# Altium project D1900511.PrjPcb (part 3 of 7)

## Sheet ISC_R2_SH2.SchDoc: ISC System Wiring Diagram
size C; DrawnBy: Filiberto Clara; Engineer: Filiberto Clara; Organization: LIGO Laboratory; Address1: California Institute of Technology; Address2: Massachusetts Institute of Technology; DocumentNumber: D1900511; Revision: V11; SheetNumber: 14; SheetTotal: 39
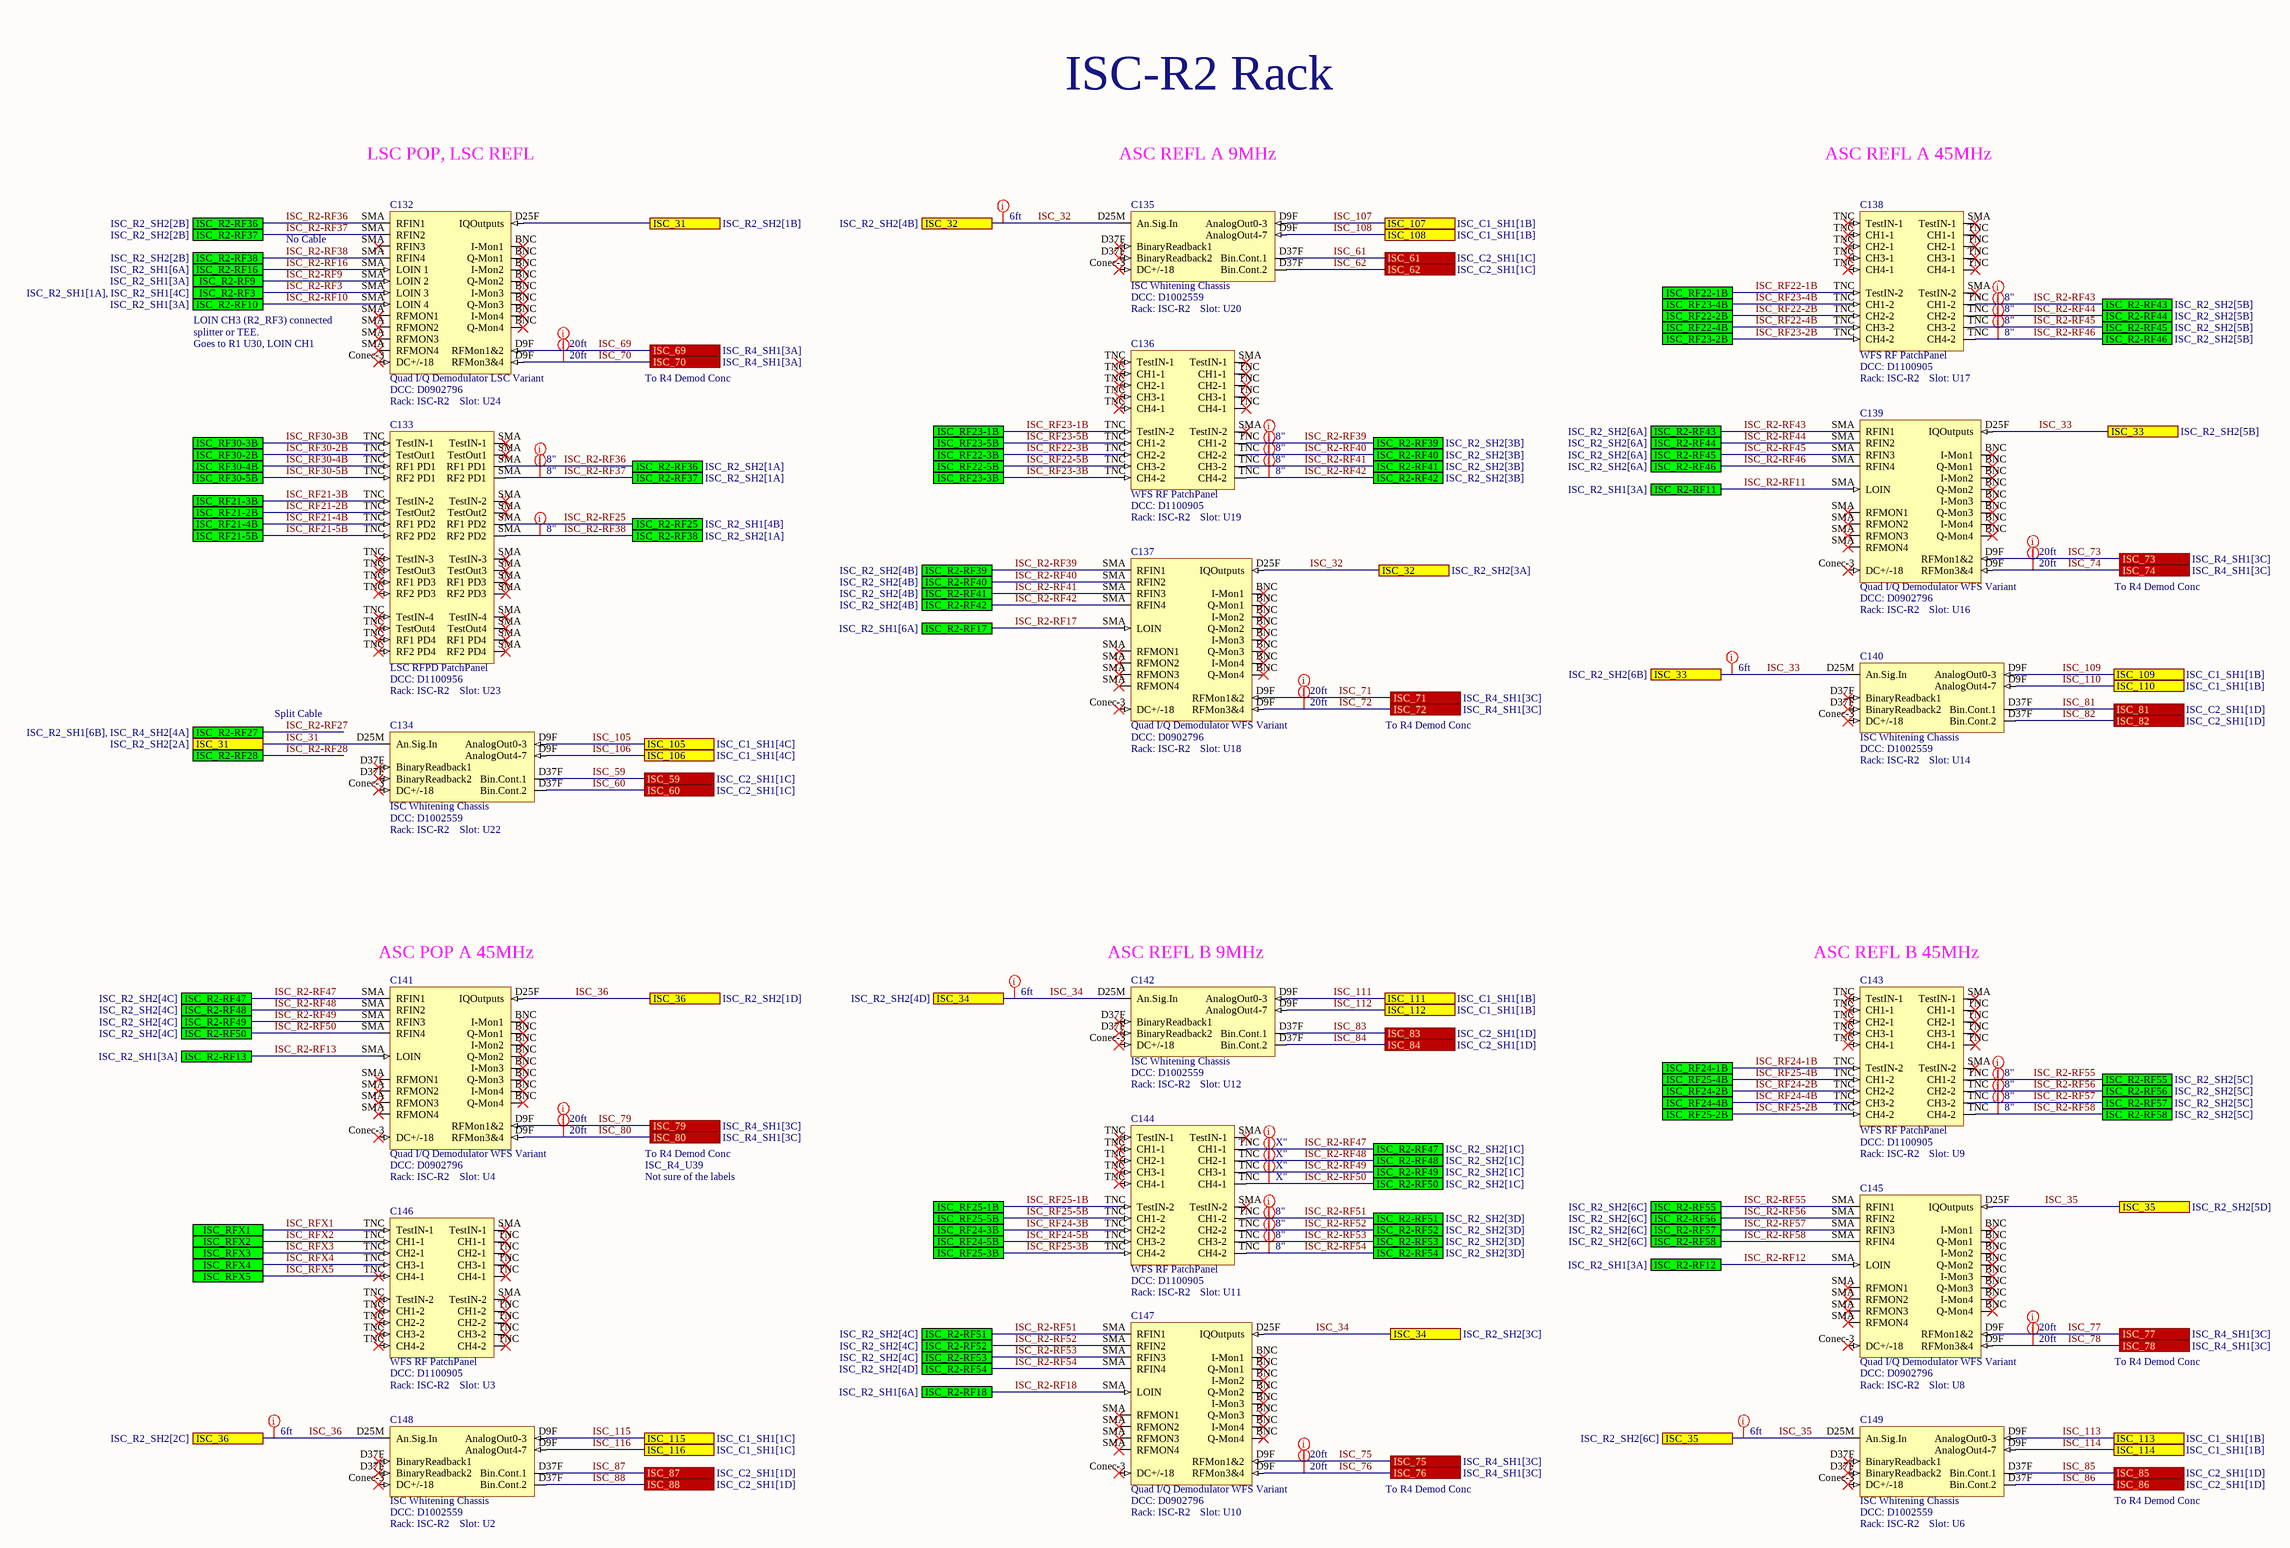
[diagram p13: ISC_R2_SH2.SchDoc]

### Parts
C132  Quad I/Q Demodulator LSC Variant  DCC: D0902796  Rack: ISC-R2  Slot: U24
C133  LSC RFPD PatchPanel  DCC: D1100956  Rack: ISC-R2  Slot: U23
C134  ISC Whitening Chassis  DCC: D1002559  Rack: ISC-R2  Slot: U22
C135  ISC Whitening Chassis  DCC: D1002559  Rack: ISC-R2  Slot: U20
C136  WFS RF PatchPanel  DCC: D1100905  Rack: ISC-R2  Slot: U19
C137  Quad I/Q Demodulator WFS Variant  DCC: D0902796  Rack: ISC-R2  Slot: U18
C138  WFS RF PatchPanel  DCC: D1100905  Rack: ISC-R2  Slot: U17
C139  Quad I/Q Demodulator WFS Variant  DCC: D0902796  Rack: ISC-R2  Slot: U16
C140  ISC Whitening Chassis  DCC: D1002559  Rack: ISC-R2  Slot: U14
C141  Quad I/Q Demodulator WFS Variant  DCC: D0902796  Rack: ISC-R2  Slot: U4
C142  ISC Whitening Chassis  DCC: D1002559  Rack: ISC-R2  Slot: U12
C143  WFS RF PatchPanel  DCC: D1100905  Rack: ISC-R2  Slot: U9
C144  WFS RF PatchPanel  DCC: D1100905  Rack: ISC-R2  Slot: U11
C145  Quad I/Q Demodulator WFS Variant  DCC: D0902796  Rack: ISC-R2  Slot: U8
C146  WFS RF PatchPanel  DCC: D1100905  Rack: ISC-R2  Slot: U3
C147  Quad I/Q Demodulator WFS Variant  DCC: D0902796  Rack: ISC-R2  Slot: U10
C148  ISC Whitening Chassis  DCC: D1002559  Rack: ISC-R2  Slot: U2
C149  ISC Whitening Chassis  DCC: D1002559  Rack: ISC-R2  Slot: U6

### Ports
ISC_31 (see ISC_R2_SH2[1B]), ISC_31 (see ISC_R2_SH2[2A]), ISC_32 (see ISC_R2_SH2[3A]), ISC_32 (see ISC_R2_SH2[4B]), ISC_33 (see ISC_R2_SH2[5B]), ISC_33 (see ISC_R2_SH2[6B]), ISC_34 (see ISC_R2_SH2[3C]), ISC_34 (see ISC_R2_SH2[4D]), ISC_35 (see ISC_R2_SH2[5D]), ISC_35 (see ISC_R2_SH2[6C]), ISC_36 (see ISC_R2_SH2[1D]), ISC_36 (see ISC_R2_SH2[2C]), ISC_59 (see ISC_C2_SH1[1C]), ISC_60 (see ISC_C2_SH1[1C]), ISC_61 (see ISC_C2_SH1[1C]), ISC_62 (see ISC_C2_SH1[1C]), ISC_69 (see ISC_R4_SH1[3A]), ISC_70 (see ISC_R4_SH1[3A]), ISC_71 (see ISC_R4_SH1[3C]), ISC_72 (see ISC_R4_SH1[3C]), ISC_73 (see ISC_R4_SH1[3C]), ISC_74 (see ISC_R4_SH1[3C]), ISC_75 (see ISC_R4_SH1[3C]), ISC_76 (see ISC_R4_SH1[3C]), ISC_77 (see ISC_R4_SH1[3C]), ISC_78 (see ISC_R4_SH1[3C]), ISC_79 (see ISC_R4_SH1[3C]), ISC_80 (see ISC_R4_SH1[3C]), ISC_81 (see ISC_C2_SH1[1D]), ISC_82 (see ISC_C2_SH1[1D]), ISC_83 (see ISC_C2_SH1[1D]), ISC_84 (see ISC_C2_SH1[1D]), ISC_85 (see ISC_C2_SH1[1D]), ISC_86 (see ISC_C2_SH1[1D]), ISC_87 (see ISC_C2_SH1[1D]), ISC_88 (see ISC_C2_SH1[1D]), ISC_105 (see ISC_C1_SH1[4C]), ISC_106 (see ISC_C1_SH1[4C]), ISC_107 (see ISC_C1_SH1[1B]), ISC_108 (see ISC_C1_SH1[1B]), ISC_109 (see ISC_C1_SH1[1B]), ISC_110 (see ISC_C1_SH1[1B]), ISC_111 (see ISC_C1_SH1[1B]), ISC_112 (see ISC_C1_SH1[1B]), ISC_113 (see ISC_C1_SH1[1B]), ISC_114 (see ISC_C1_SH1[1B]), ISC_115 (see ISC_C1_SH1[1C]), ISC_116 (see ISC_C1_SH1[1C]), ISC_R2-RF3 (see ISC_R2_SH1[1A], ISC_R2_SH1[4C]), ISC_R2-RF9 (see ISC_R2_SH1[3A]), ISC_R2-RF10 (see ISC_R2_SH1[3A]), ISC_R2-RF11 (see ISC_R2_SH1[3A]), ISC_R2-RF12 (see ISC_R2_SH1[3A]), ISC_R2-RF13 (see ISC_R2_SH1[3A]), ISC_R2-RF16 (see ISC_R2_SH1[6A]), ISC_R2-RF17 (see ISC_R2_SH1[6A]), ISC_R2-RF18 (see ISC_R2_SH1[6A]), ISC_R2-RF25 (see ISC_R2_SH1[4B]), ISC_R2-RF27 (see ISC_R2_SH1[6B], ISC_R4_SH2[4A]), ISC_R2-RF28, ISC_R2-RF36 (see ISC_R2_SH2[1A]), ISC_R2-RF36 (see ISC_R2_SH2[2B]), ISC_R2-RF37 (see ISC_R2_SH2[1A]), ISC_R2-RF37 (see ISC_R2_SH2[2B]), ISC_R2-RF38 (see ISC_R2_SH2[1A]), ISC_R2-RF38 (see ISC_R2_SH2[2B]), ISC_R2-RF39 (see ISC_R2_SH2[3B]), ISC_R2-RF39 (see ISC_R2_SH2[4B]), ISC_R2-RF40 (see ISC_R2_SH2[3B]), ISC_R2-RF40 (see ISC_R2_SH2[4B]), ISC_R2-RF41 (see ISC_R2_SH2[3B]), ISC_R2-RF41 (see ISC_R2_SH2[4B]), ISC_R2-RF42 (see ISC_R2_SH2[3B]), ISC_R2-RF42 (see ISC_R2_SH2[4B]), ISC_R2-RF43 (see ISC_R2_SH2[5B]), ISC_R2-RF43 (see ISC_R2_SH2[6A]), ISC_R2-RF44 (see ISC_R2_SH2[5B]), ISC_R2-RF44 (see ISC_R2_SH2[6A]), ISC_R2-RF45 (see ISC_R2_SH2[5B]), ISC_R2-RF45 (see ISC_R2_SH2[6A]), ISC_R2-RF46 (see ISC_R2_SH2[5B]), ISC_R2-RF46 (see ISC_R2_SH2[6A]), ISC_R2-RF47 (see ISC_R2_SH2[1C]), ISC_R2-RF47 (see ISC_R2_SH2[4C]), ISC_R2-RF48 (see ISC_R2_SH2[1C]), ISC_R2-RF48 (see ISC_R2_SH2[4C]), ISC_R2-RF49 (see ISC_R2_SH2[1C]), ISC_R2-RF49 (see ISC_R2_SH2[4C]), ISC_R2-RF50 (see ISC_R2_SH2[1C]), ISC_R2-RF50 (see ISC_R2_SH2[4C]), ISC_R2-RF51 (see ISC_R2_SH2[3D]), ISC_R2-RF51 (see ISC_R2_SH2[4C]), ISC_R2-RF52 (see ISC_R2_SH2[3D]), ISC_R2-RF52 (see ISC_R2_SH2[4C]), ISC_R2-RF53 (see ISC_R2_SH2[3D]), ISC_R2-RF53 (see ISC_R2_SH2[4C]), ISC_R2-RF54 (see ISC_R2_SH2[3D]), ISC_R2-RF54 (see ISC_R2_SH2[4D]), ISC_R2-RF55 (see ISC_R2_SH2[5C]), ISC_R2-RF55 (see ISC_R2_SH2[6C]), ISC_R2-RF56 (see ISC_R2_SH2[5C]), ISC_R2-RF56 (see ISC_R2_SH2[6C]), ISC_R2-RF57 (see ISC_R2_SH2[5C]), ISC_R2-RF57 (see ISC_R2_SH2[6C]), ISC_R2-RF58 (see ISC_R2_SH2[5C]), ISC_R2-RF58 (see ISC_R2_SH2[6C]), ISC_RF21-2B, ISC_RF21-3B, ISC_RF21-4B, ISC_RF21-5B, ISC_RF22-1B, ISC_RF22-2B, ISC_RF22-3B, ISC_RF22-4B, ISC_RF22-5B, ISC_RF23-1B, ISC_RF23-2B, ISC_RF23-3B, ISC_RF23-4B, ISC_RF23-5B, ISC_RF24-1B, ISC_RF24-2B, ISC_RF24-3B, ISC_RF24-4B, ISC_RF24-5B, ISC_RF25-1B, ISC_RF25-2B, ISC_RF25-3B, ISC_RF25-4B, ISC_RF25-5B, ISC_RF30-2B, ISC_RF30-3B, ISC_RF30-4B, ISC_RF30-5B, ISC_RFX1, ISC_RFX2, ISC_RFX3, ISC_RFX4, ISC_RFX5

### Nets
ISC_31: C132.D25F(IQOutputs) C134.D25M(An.Sig.In) ; port ISC_31
ISC_32: C135.D25M(An.Sig.In) C137.D25F(IQOutputs) ; port ISC_32
ISC_33: C139.D25F(IQOutputs) C140.D25M(An.Sig.In) ; port ISC_33
ISC_34: C142.D25M(An.Sig.In) C147.D25F(IQOutputs) ; port ISC_34
ISC_35: C145.D25F(IQOutputs) C149.D25M(An.Sig.In) ; port ISC_35
ISC_36: C141.D25F(IQOutputs) C148.D25M(An.Sig.In) ; port ISC_36
ISC_59: C134.D37F(BinaryReadback1) ; port ISC_59
ISC_60: C134.D37F(Bin.Cont.2) ; port ISC_60
ISC_61: C135.D37F(BinaryReadback1) ; port ISC_61
ISC_62: C135.D37F(Bin.Cont.2) ; port ISC_62
ISC_69: C132.D9F(RFMon1&2) ; port ISC_69
ISC_70: C132.D9F(RFMon3&4) ; port ISC_70
ISC_71: C137.D9F(RFMon1&2) ; port ISC_71
ISC_72: C137.D9F(RFMon3&4) ; port ISC_72
ISC_73: C139.D9F(RFMon1&2) ; port ISC_73
ISC_74: C139.D9F(RFMon3&4) ; port ISC_74
ISC_75: C147.D9F(RFMon1&2) ; port ISC_75
ISC_76: C147.D9F(RFMon3&4) ; port ISC_76
ISC_77: C145.D9F(RFMon1&2) ; port ISC_77
ISC_78: C145.D9F(RFMon3&4) ; port ISC_78
ISC_79: C141.D9F(RFMon1&2) ; port ISC_79
ISC_80: C141.D9F(RFMon3&4) ; port ISC_80
ISC_81: C140.D37F(BinaryReadback1) ; port ISC_81
ISC_82: C140.D37F(Bin.Cont.2) ; port ISC_82
ISC_83: C142.D37F(BinaryReadback1) ; port ISC_83
ISC_84: C142.D37F(Bin.Cont.2) ; port ISC_84
ISC_85: C149.D37F(BinaryReadback1) ; port ISC_85
ISC_86: C149.D37F(Bin.Cont.2) ; port ISC_86
ISC_87: C148.D37F(BinaryReadback1) ; port ISC_87
ISC_88: C148.D37F(Bin.Cont.2) ; port ISC_88
ISC_105: C134.D9F(AnalogOut0-3) ; port ISC_105
ISC_106: C134.D9F(AnalogOut4-7) ; port ISC_106
ISC_107: C135.D9F(AnalogOut0-3) ; port ISC_107
ISC_108: C135.D9F(AnalogOut4-7) ; port ISC_108
ISC_109: C140.D9F(AnalogOut0-3) ; port ISC_109
ISC_110: C140.D9F(AnalogOut4-7) ; port ISC_110
ISC_111: C142.D9F(AnalogOut0-3) ; port ISC_111
ISC_112: C142.D9F(AnalogOut4-7) ; port ISC_112
ISC_113: C149.D9F(AnalogOut0-3) ; port ISC_113
ISC_114: C149.D9F(AnalogOut4-7) ; port ISC_114
ISC_115: C148.D9F(AnalogOut0-3) ; port ISC_115
ISC_116: C148.D9F(AnalogOut4-7) ; port ISC_116
ISC_R2-RF3: C132.SMA(LOIN_3) ; port ISC_R2-RF3
ISC_R2-RF9: C132.SMA(LOIN_2) ; port ISC_R2-RF9
ISC_R2-RF10: C132.SMA(LOIN_4) ; port ISC_R2-RF10
ISC_R2-RF11: C139.SMA(LOIN) ; port ISC_R2-RF11
ISC_R2-RF12: C145.SMA(LOIN) ; port ISC_R2-RF12
ISC_R2-RF13: C141.SMA(LOIN) ; port ISC_R2-RF13
ISC_R2-RF16: C132.SMA(LOIN_1) ; port ISC_R2-RF16
ISC_R2-RF17: C137.SMA(LOIN) ; port ISC_R2-RF17
ISC_R2-RF18: C147.SMA(LOIN) ; port ISC_R2-RF18
ISC_R2-RF25: C133.SMA(RF1_PD2) ; port ISC_R2-RF25
ISC_R2-RF36: C132.SMA(RFIN1) C133.SMA(TestIN-1) ; port ISC_R2-RF36
ISC_R2-RF37: C132.SMA(RFIN2) C133.SMA(RF2_PD1) ; port ISC_R2-RF37
ISC_R2-RF38: C132.SMA(RFIN4) C133.SMA(RF2_PD2) ; port ISC_R2-RF38
ISC_R2-RF39: C136.TNC(CH1-2) C137.SMA(RFIN1) ; port ISC_R2-RF39
ISC_R2-RF40: C136.TNC(CH2-2) C137.SMA(RFIN2) ; port ISC_R2-RF40
ISC_R2-RF41: C136.TNC(CH3-2) C137.SMA(RFIN3) ; port ISC_R2-RF41
ISC_R2-RF42: C136.TNC(CH4-2) C137.SMA(RFIN4) ; port ISC_R2-RF42
ISC_R2-RF43: C138.TNC(CH1-2) C139.SMA(RFIN1) ; port ISC_R2-RF43
ISC_R2-RF44: C138.TNC(CH2-2) C139.SMA(RFIN2) ; port ISC_R2-RF44
ISC_R2-RF45: C138.TNC(CH3-2) C139.SMA(RFIN3) ; port ISC_R2-RF45
ISC_R2-RF46: C138.TNC(CH4-2) C139.SMA(RFIN4) ; port ISC_R2-RF46
ISC_R2-RF47: C141.SMA(RFIN1) C144.TNC(CH1-1) ; port ISC_R2-RF47
ISC_R2-RF48: C141.SMA(RFIN2) C144.TNC(CH2-1) ; port ISC_R2-RF48
ISC_R2-RF49: C141.SMA(RFIN3) C144.TNC(CH3-1) ; port ISC_R2-RF49
ISC_R2-RF50: C141.SMA(RFIN4) C144.TNC(CH4-1) ; port ISC_R2-RF50
ISC_R2-RF51: C144.TNC(CH1-2) C147.SMA(RFIN1) ; port ISC_R2-RF51
ISC_R2-RF52: C144.TNC(CH2-2) C147.SMA(RFIN2) ; port ISC_R2-RF52
ISC_R2-RF53: C144.TNC(CH3-2) C147.SMA(RFIN3) ; port ISC_R2-RF53
ISC_R2-RF54: C144.TNC(CH4-2) C147.SMA(RFIN4) ; port ISC_R2-RF54
ISC_R2-RF55: C143.TNC(CH1-2) C145.SMA(RFIN1) ; port ISC_R2-RF55
ISC_R2-RF56: C143.TNC(CH2-2) C145.SMA(RFIN2) ; port ISC_R2-RF56
ISC_R2-RF57: C143.TNC(CH3-2) C145.SMA(RFIN3) ; port ISC_R2-RF57
ISC_R2-RF58: C143.TNC(CH4-2) C145.SMA(RFIN4) ; port ISC_R2-RF58
ISC_RF21-2B: C133.TNC(TestOut2) ; port ISC_RF21-2B
ISC_RF21-3B: C133.TNC(TestIN-2) ; port ISC_RF21-3B
ISC_RF21-4B: C133.TNC(RF1_PD2) ; port ISC_RF21-4B
ISC_RF21-5B: C133.TNC(RF2_PD2) ; port ISC_RF21-5B
ISC_RF22-1B: C138.TNC(TestIN-1) ; port ISC_RF22-1B
ISC_RF22-2B: C138.TNC(CH2-2) ; port ISC_RF22-2B
ISC_RF22-3B: C136.TNC(CH2-2) ; port ISC_RF22-3B
ISC_RF22-4B: C138.TNC(CH3-2) ; port ISC_RF22-4B
ISC_RF22-5B: C136.TNC(CH3-2) ; port ISC_RF22-5B
ISC_RF23-1B: C136.TNC(TestIN-1) ; port ISC_RF23-1B
ISC_RF23-2B: C138.TNC(CH4-2) ; port ISC_RF23-2B
ISC_RF23-3B: C136.TNC(CH4-2) ; port ISC_RF23-3B
ISC_RF23-4B: C138.TNC(CH1-2) ; port ISC_RF23-4B
ISC_RF23-5B: C136.TNC(CH1-2) ; port ISC_RF23-5B
ISC_RF24-1B: C143.TNC(TestIN-1) ; port ISC_RF24-1B
ISC_RF24-2B: C143.TNC(CH2-2) ; port ISC_RF24-2B
ISC_RF24-3B: C144.TNC(CH2-2) ; port ISC_RF24-3B
ISC_RF24-4B: C143.TNC(CH3-2) ; port ISC_RF24-4B
ISC_RF24-5B: C144.TNC(CH3-2) ; port ISC_RF24-5B
ISC_RF25-1B: C144.TNC(TestIN-1) ; port ISC_RF25-1B
ISC_RF25-2B: C143.TNC(CH4-2) ; port ISC_RF25-2B
ISC_RF25-3B: C144.TNC(CH4-2) ; port ISC_RF25-3B
ISC_RF25-4B: C143.TNC(CH1-2) ; port ISC_RF25-4B
ISC_RF25-5B: C144.TNC(CH1-2) ; port ISC_RF25-5B
ISC_RF30-2B: C133.TNC(TestOut1) ; port ISC_RF30-2B
ISC_RF30-3B: C133.TNC(TestIN-1) ; port ISC_RF30-3B
ISC_RF30-4B: C133.TNC(RF1_PD1) ; port ISC_RF30-4B
ISC_RF30-5B: C133.TNC(RF2_PD1) ; port ISC_RF30-5B
ISC_RFX1: C146.TNC(TestIN-1) ; port ISC_RFX1
ISC_RFX2: C146.TNC(CH1-1) ; port ISC_RFX2
ISC_RFX3: C146.TNC(CH2-1) ; port ISC_RFX3
ISC_RFX4: C146.TNC(CH3-1) ; port ISC_RFX4
ISC_RFX5: C146.TNC(CH4-1) ; port ISC_RFX5

Not connected (* = marked no-connect by the designer): C132 BNC(I-Mon1)* Conec-3(DC+/-18)*; C134 Conec-3(DC+/-18)*; C135 Conec-3(DC+/-18)*; C136 SMA(TestIN-1)*; C137 BNC(I-Mon1)* Conec-3(DC+/-18)*; C138 SMA(TestIN-1)*; C139 BNC(I-Mon1)* Conec-3(DC+/-18)*; C140 Conec-3(DC+/-18)*; C141 BNC(I-Mon1)* Conec-3(DC+/-18)*; C142 Conec-3(DC+/-18)*; C143 SMA(TestIN-1)*; C144 SMA(TestIN-1)*; C145 BNC(I-Mon1)* Conec-3(DC+/-18)*; C146 SMA(TestIN-1)*; C147 BNC(I-Mon1)* Conec-3(DC+/-18)*; C148 Conec-3(DC+/-18)*; C149 Conec-3(DC+/-18)*

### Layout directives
Length: 6ft: ISC_32, ISC_33, ISC_34, ISC_35, ISC_36
Length: 20ft: ISC_69, ISC_70, ISC_71, ISC_72, ISC_73, ISC_74, ISC_75, ISC_76, ISC_77, ISC_78, ISC_79, ISC_80
Length: 8": ISC_R2-RF36, ISC_R2-RF37, ISC_R2-RF38, ISC_R2-RF39, ISC_R2-RF40, ISC_R2-RF41, ISC_R2-RF42, ISC_R2-RF43, ISC_R2-RF44, ISC_R2-RF45, ISC_R2-RF46, ISC_R2-RF51, ISC_R2-RF52, ISC_R2-RF53, ISC_R2-RF54, ISC_R2-RF55, ISC_R2-RF56, ISC_R2-RF57, ISC_R2-RF58
Length: X": ISC_R2-RF47, ISC_R2-RF48, ISC_R2-RF49, ISC_R2-RF50

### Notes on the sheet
- ISC-R2 Rack
- LSC POP, LSC REFL
- ASC REFL A 9MHz
- ASC REFL A 45MHz
- No Cable
- LOIN CH3 (R2_RF3) connected
- splitter or TEE.
- Goes to R1 U30, LOIN CH1
- To R4 Demod Conc
- Split Cable
- (near C141) ASC POP A 45MHz
- (near C142) ASC REFL B 9MHz
- (near C143) ASC REFL B 45MHz
- ISC_R4_U39
- Not sure of the labels

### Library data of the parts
C132 = QuadIQdemod_LSC: Serial: Sxxxxxxx; System: ISC
C133 = LSC RFPD PatchPanel: Serial: Sxxxxxxx; System: ISC
C134 C135 C140 C142 C148 C149 = ISC Whitening: Serial: Sxxxxxxx
C136 C138 C143 C144 C146 = WFS RFPD PatchPanel: Serial: Sxxxxxxx; System: ISC
C137 C139 C141 C145 C147 = QuadIQdemod_WFS: Serial: Sxxxxxxx; System: ISC

## Sheet ISC_R4_SH1.SchDoc: ISC System Wiring Diagram
size B; DrawnBy: Filiberto Clara; Engineer: Filiberto Clara; Organization: LIGO Laboratory; Address1: California Institute of Technology; Address2: Massachusetts Institute of Technology; DocumentNumber: D1900511; Revision: V11; SheetNumber: 15; SheetTotal: 39
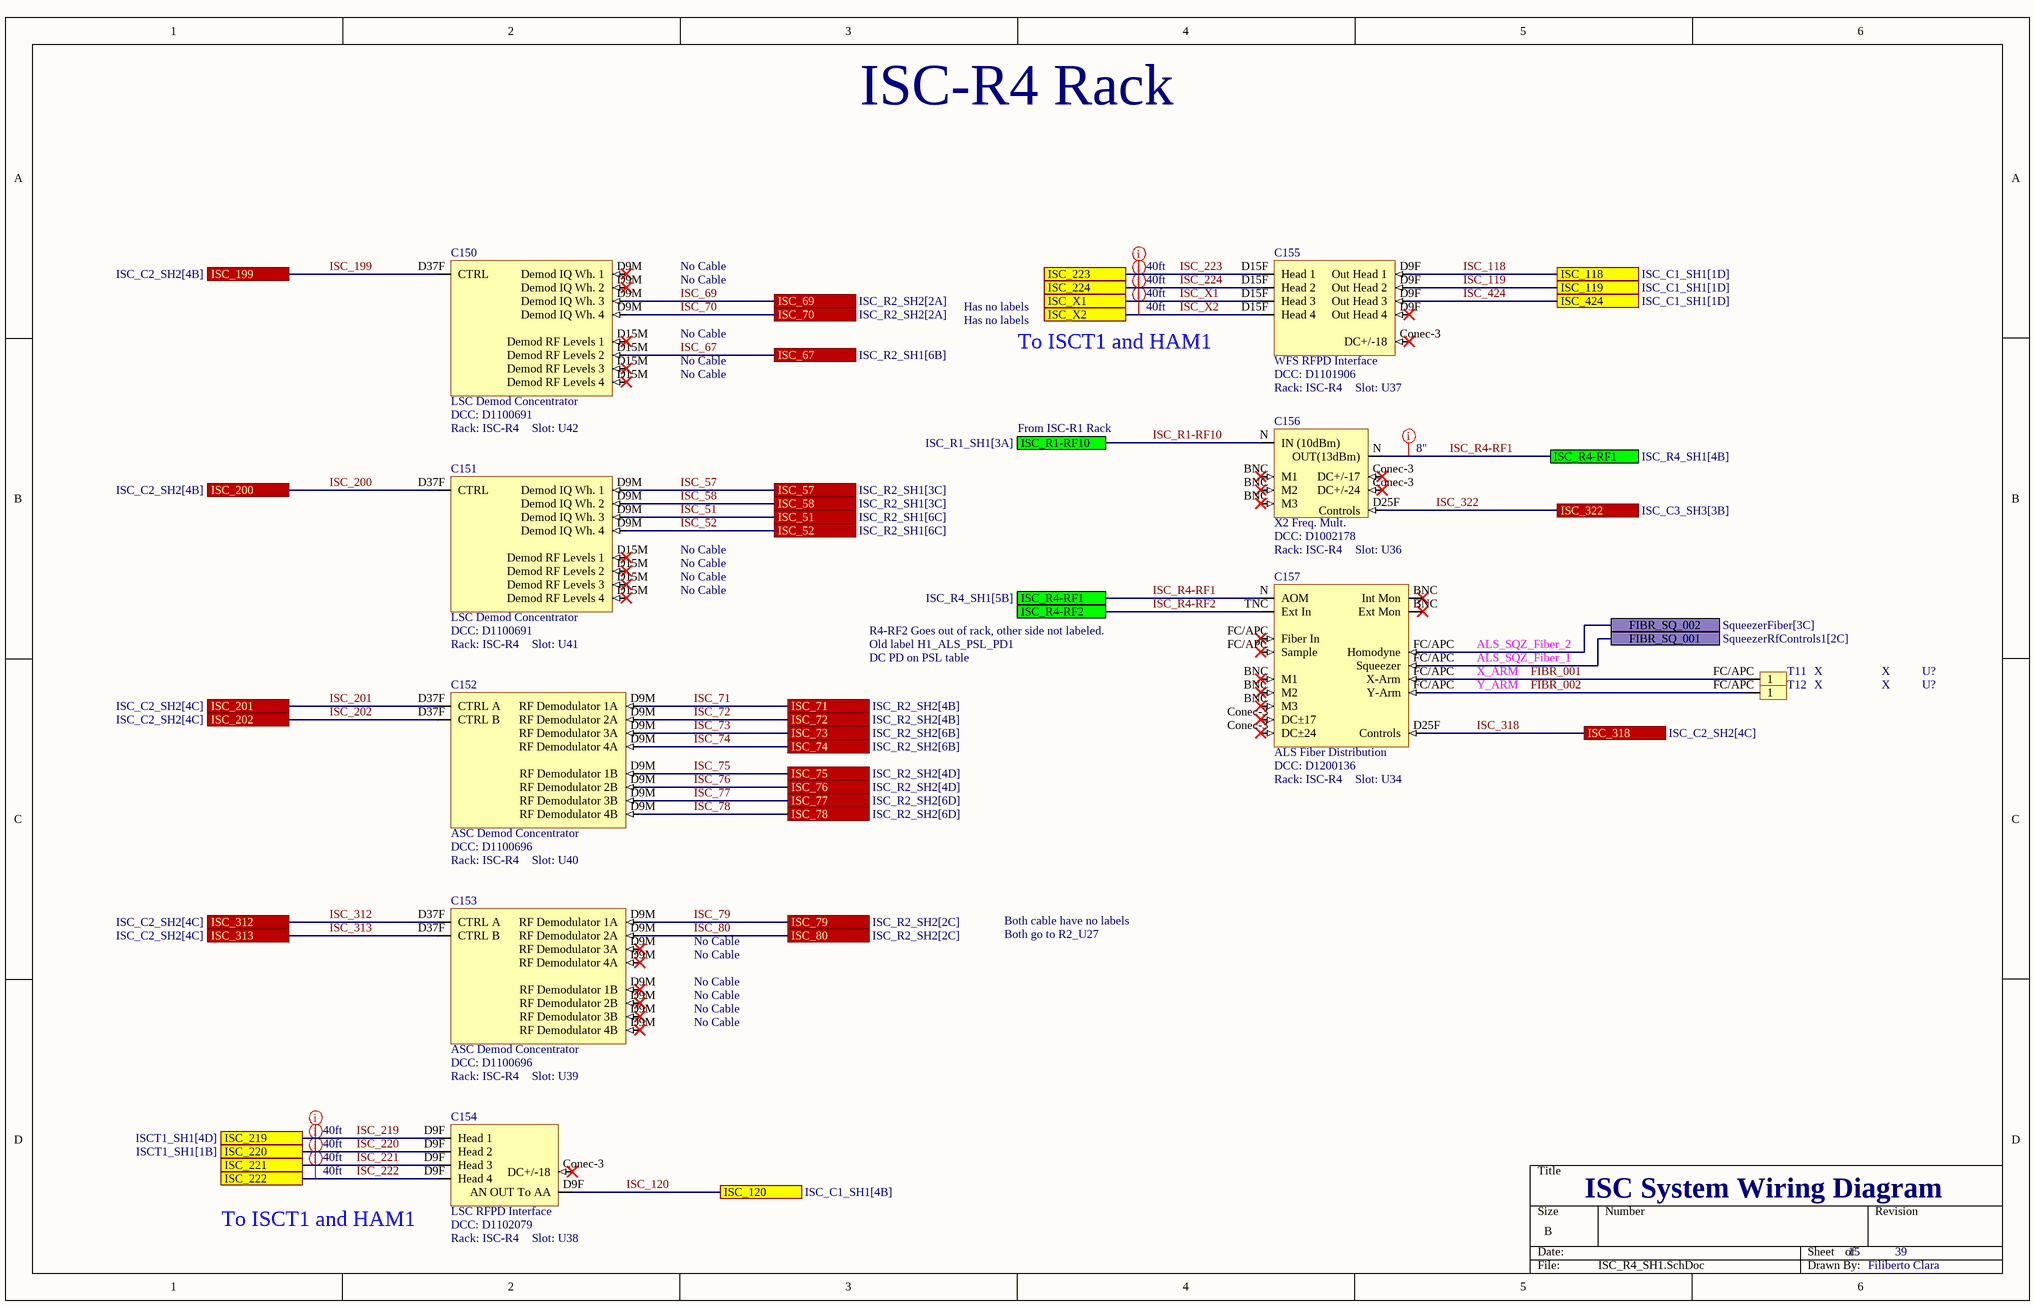
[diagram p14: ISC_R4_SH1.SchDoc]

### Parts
C150  LSC Demod Concentrator  DCC: D1100691  Rack: ISC-R4  Slot: U42
C151  LSC Demod Concentrator  DCC: D1100691  Rack: ISC-R4  Slot: U41
C152  ASC Demod Concentrator  DCC: D1100696  Rack: ISC-R4  Slot: U40
C153  ASC Demod Concentrator  DCC: D1100696  Rack: ISC-R4  Slot: U39
C154  LSC RFPD Interface  DCC: D1102079  Rack: ISC-R4  Slot: U38
C155  WFS RFPD Interface  DCC: D1101906  Rack: ISC-R4  Slot: U37
C156  X2 Freq. Mult.  DCC: D1002178  Rack: ISC-R4  Slot: U36
C157  ALS Fiber Distribution  DCC: D1200136  Rack: ISC-R4  Slot: U34
T11  X  Slot: U?
T12  X  Slot: U?

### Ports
FIBR_SQ_001 (see SqueezerRfControls1[2C]), FIBR_SQ_002 (see SqueezerFiber[3C]), ISC_51 (see ISC_R2_SH1[6C]), ISC_52 (see ISC_R2_SH1[6C]), ISC_57 (see ISC_R2_SH1[3C]), ISC_58 (see ISC_R2_SH1[3C]), ISC_67 (see ISC_R2_SH1[6B]), ISC_69 (see ISC_R2_SH2[2A]), ISC_70 (see ISC_R2_SH2[2A]), ISC_71 (see ISC_R2_SH2[4B]), ISC_72 (see ISC_R2_SH2[4B]), ISC_73 (see ISC_R2_SH2[6B]), ISC_74 (see ISC_R2_SH2[6B]), ISC_75 (see ISC_R2_SH2[4D]), ISC_76 (see ISC_R2_SH2[4D]), ISC_77 (see ISC_R2_SH2[6D]), ISC_78 (see ISC_R2_SH2[6D]), ISC_79 (see ISC_R2_SH2[2C]), ISC_80 (see ISC_R2_SH2[2C]), ISC_118 (see ISC_C1_SH1[1D]), ISC_119 (see ISC_C1_SH1[1D]), ISC_120 (see ISC_C1_SH1[4B]), ISC_199 (see ISC_C2_SH2[4B]), ISC_200 (see ISC_C2_SH2[4B]), ISC_201 (see ISC_C2_SH2[4C]), ISC_202 (see ISC_C2_SH2[4C]), ISC_219 (see ISCT1_SH1[4D]), ISC_220 (see ISCT1_SH1[1B]), ISC_221, ISC_222, ISC_223, ISC_224, ISC_312 (see ISC_C2_SH2[4C]), ISC_313 (see ISC_C2_SH2[4C]), ISC_318 (see ISC_C2_SH2[4C]), ISC_322 (see ISC_C3_SH3[3B]), ISC_424 (see ISC_C1_SH1[1D]), ISC_R1-RF10 (see ISC_R1_SH1[3A]), ISC_R4-RF1 (see ISC_R4_SH1[4B]), ISC_R4-RF1 (see ISC_R4_SH1[5B]), ISC_R4-RF2, ISC_X1, ISC_X2

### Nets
FIBR_001: C157.FC/APC(Fiber_In) T11.FC/APC(1)
FIBR_002: C157.FC/APC(Y-Arm) T12.FC/APC(1)
FIBR_SQ_001: C157.FC/APC(Squeezer) ; port FIBR_SQ_001
FIBR_SQ_002: C157.FC/APC(Homodyne) ; port FIBR_SQ_002
ISC_51: C151.D9M(Demod_IQ_Wh._3) ; port ISC_51
ISC_52: C151.D9M(Demod_IQ_Wh._4) ; port ISC_52
ISC_57: C151.D9M(Demod_IQ_Wh._1) ; port ISC_57
ISC_58: C151.D9M(Demod_IQ_Wh._2) ; port ISC_58
ISC_67: C150.D15M(Demod_RF_Levels_1) ; port ISC_67
ISC_69: C150.D9M(Demod_IQ_Wh._1) ; port ISC_69
ISC_70: C150.D9M(Demod_IQ_Wh._4) ; port ISC_70
ISC_71: C152.D9M(RF_Demodulator_1A) ; port ISC_71
ISC_72: C152.D9M(RF_Demodulator_2A) ; port ISC_72
ISC_73: C152.D9M(RF_Demodulator_3A) ; port ISC_73
ISC_74: C152.D9M(RF_Demodulator_4A) ; port ISC_74
ISC_75: C152.D9M(RF_Demodulator_1B) ; port ISC_75
ISC_76: C152.D9M(RF_Demodulator_2B) ; port ISC_76
ISC_77: C152.D9M(RF_Demodulator_3B) ; port ISC_77
ISC_78: C152.D9M(RF_Demodulator_4B) ; port ISC_78
ISC_79: C153.D9M(RF_Demodulator_1A) ; port ISC_79
ISC_80: C153.D9M(RF_Demodulator_2A) ; port ISC_80
ISC_118: C155.D9F(Out_Head_1) ; port ISC_118
ISC_119: C155.D9F(Out_Head_2) ; port ISC_119
ISC_120: C154.D9F(AN_OUT_To_AA) ; port ISC_120
ISC_199: C150.D37F(CTRL) ; port ISC_199
ISC_200: C151.D37F(CTRL) ; port ISC_200
ISC_201: C152.D37F(CTRL_A) ; port ISC_201
ISC_202: C152.D37F(CTRL_B) ; port ISC_202
ISC_219: C154.D9F(Head_1) ; port ISC_219
ISC_220: C154.D9F(Head_2) ; port ISC_220
ISC_221: C154.D9F(Head_3) ; port ISC_221
ISC_222: C154.D9F(Head_4) ; port ISC_222
ISC_223: C155.D15F(Head_1) ; port ISC_223
ISC_224: C155.D15F(Head_2) ; port ISC_224
ISC_312: C153.D37F(CTRL_A) ; port ISC_312
ISC_313: C153.D37F(CTRL_B) ; port ISC_313
ISC_318: C157.D25F(Controls) ; port ISC_318
ISC_322: C156.D25F(Controls) ; port ISC_322
ISC_424: C155.D9F(Out_Head_3) ; port ISC_424
ISC_R1-RF10: C156.N(IN_(10dBm)) ; port ISC_R1-RF10
ISC_R4-RF1: C156.N(OUT(13dBm)) C157.N(AOM) ; port ISC_R4-RF1
ISC_R4-RF2: C157.TNC(Ext_In) ; port ISC_R4-RF2
ISC_X1: C155.D15F(Head_3) ; port ISC_X1
ISC_X2: C155.D15F(Head_4) ; port ISC_X2

Not connected (* = marked no-connect by the designer): C151 D15M(Demod_RF_Levels_1)*; C154 Conec-3(DC+/-18)*; C155 Conec-3(DC+/-18)*; C156 BNC(M1)* Conec-3(DC+/-17)*; C157 BNC(Int_Mon)* Conec-3(DC±17)*

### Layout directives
Length: 40ft: ISC_219, ISC_220, ISC_221, ISC_222, ISC_223, ISC_224, ISC_X1, ISC_X2
Length: 8": ISC_R4-RF1

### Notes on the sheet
- ISC-R4 Rack
- No Cable
- Has no labels
- To ISCT1 and HAM1
- From ISC-R1 Rack
- R4-RF2 Goes out of rack, other side not labeled.
- Old label H1_ALS_PSL_PD1
- ALS_SQZ_Fiber_2
- DC PD on PSL table
- ALS_SQZ_Fiber_1
- X_ARM
- Y_ARM
- Both cable have no labels
- Both go to R2_U27
- (near C154) To ISCT1 and HAM1

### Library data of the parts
C150 C151 = LSC Demod Concentrator: Serial: Sxxxxxxx; System: ISC
C152 C153 = ASC Demod Concentrator: Serial: Sxxxxxxx; System: ISC
C154 = LSC RFPD Interface: Serial: Sxxxxxxx; System: ISC
C155 = WFS RFPD Interface: Serial: Sxxxxxxx; System: ISC
C156 = X2 Freq. Mult.: Serial: Sxxxxxxx; System: ISC
C157 = ALS Fiber Distribution_V6: Serial: Sxxxxxxx; System: ISC
T11 = Placeholder: Place Holder; Serial: Sxxxxxxx; System: ISC; DCC: tbd
T12 = Placeholder: Serial: Sxxxxxxx; System: ISC; DCC: tbd

## Sheet ISC_R4_SH2.SchDoc: ISC System Wiring Diagram
size C; DrawnBy: Filiberto Clara; Engineer: Filiberto Clara; Organization: LIGO Laboratory; Address1: California Institute of Technology; Address2: Massachusetts Institute of Technology; DocumentNumber: D1900511; Revision: V11; SheetNumber: 16; SheetTotal: 39
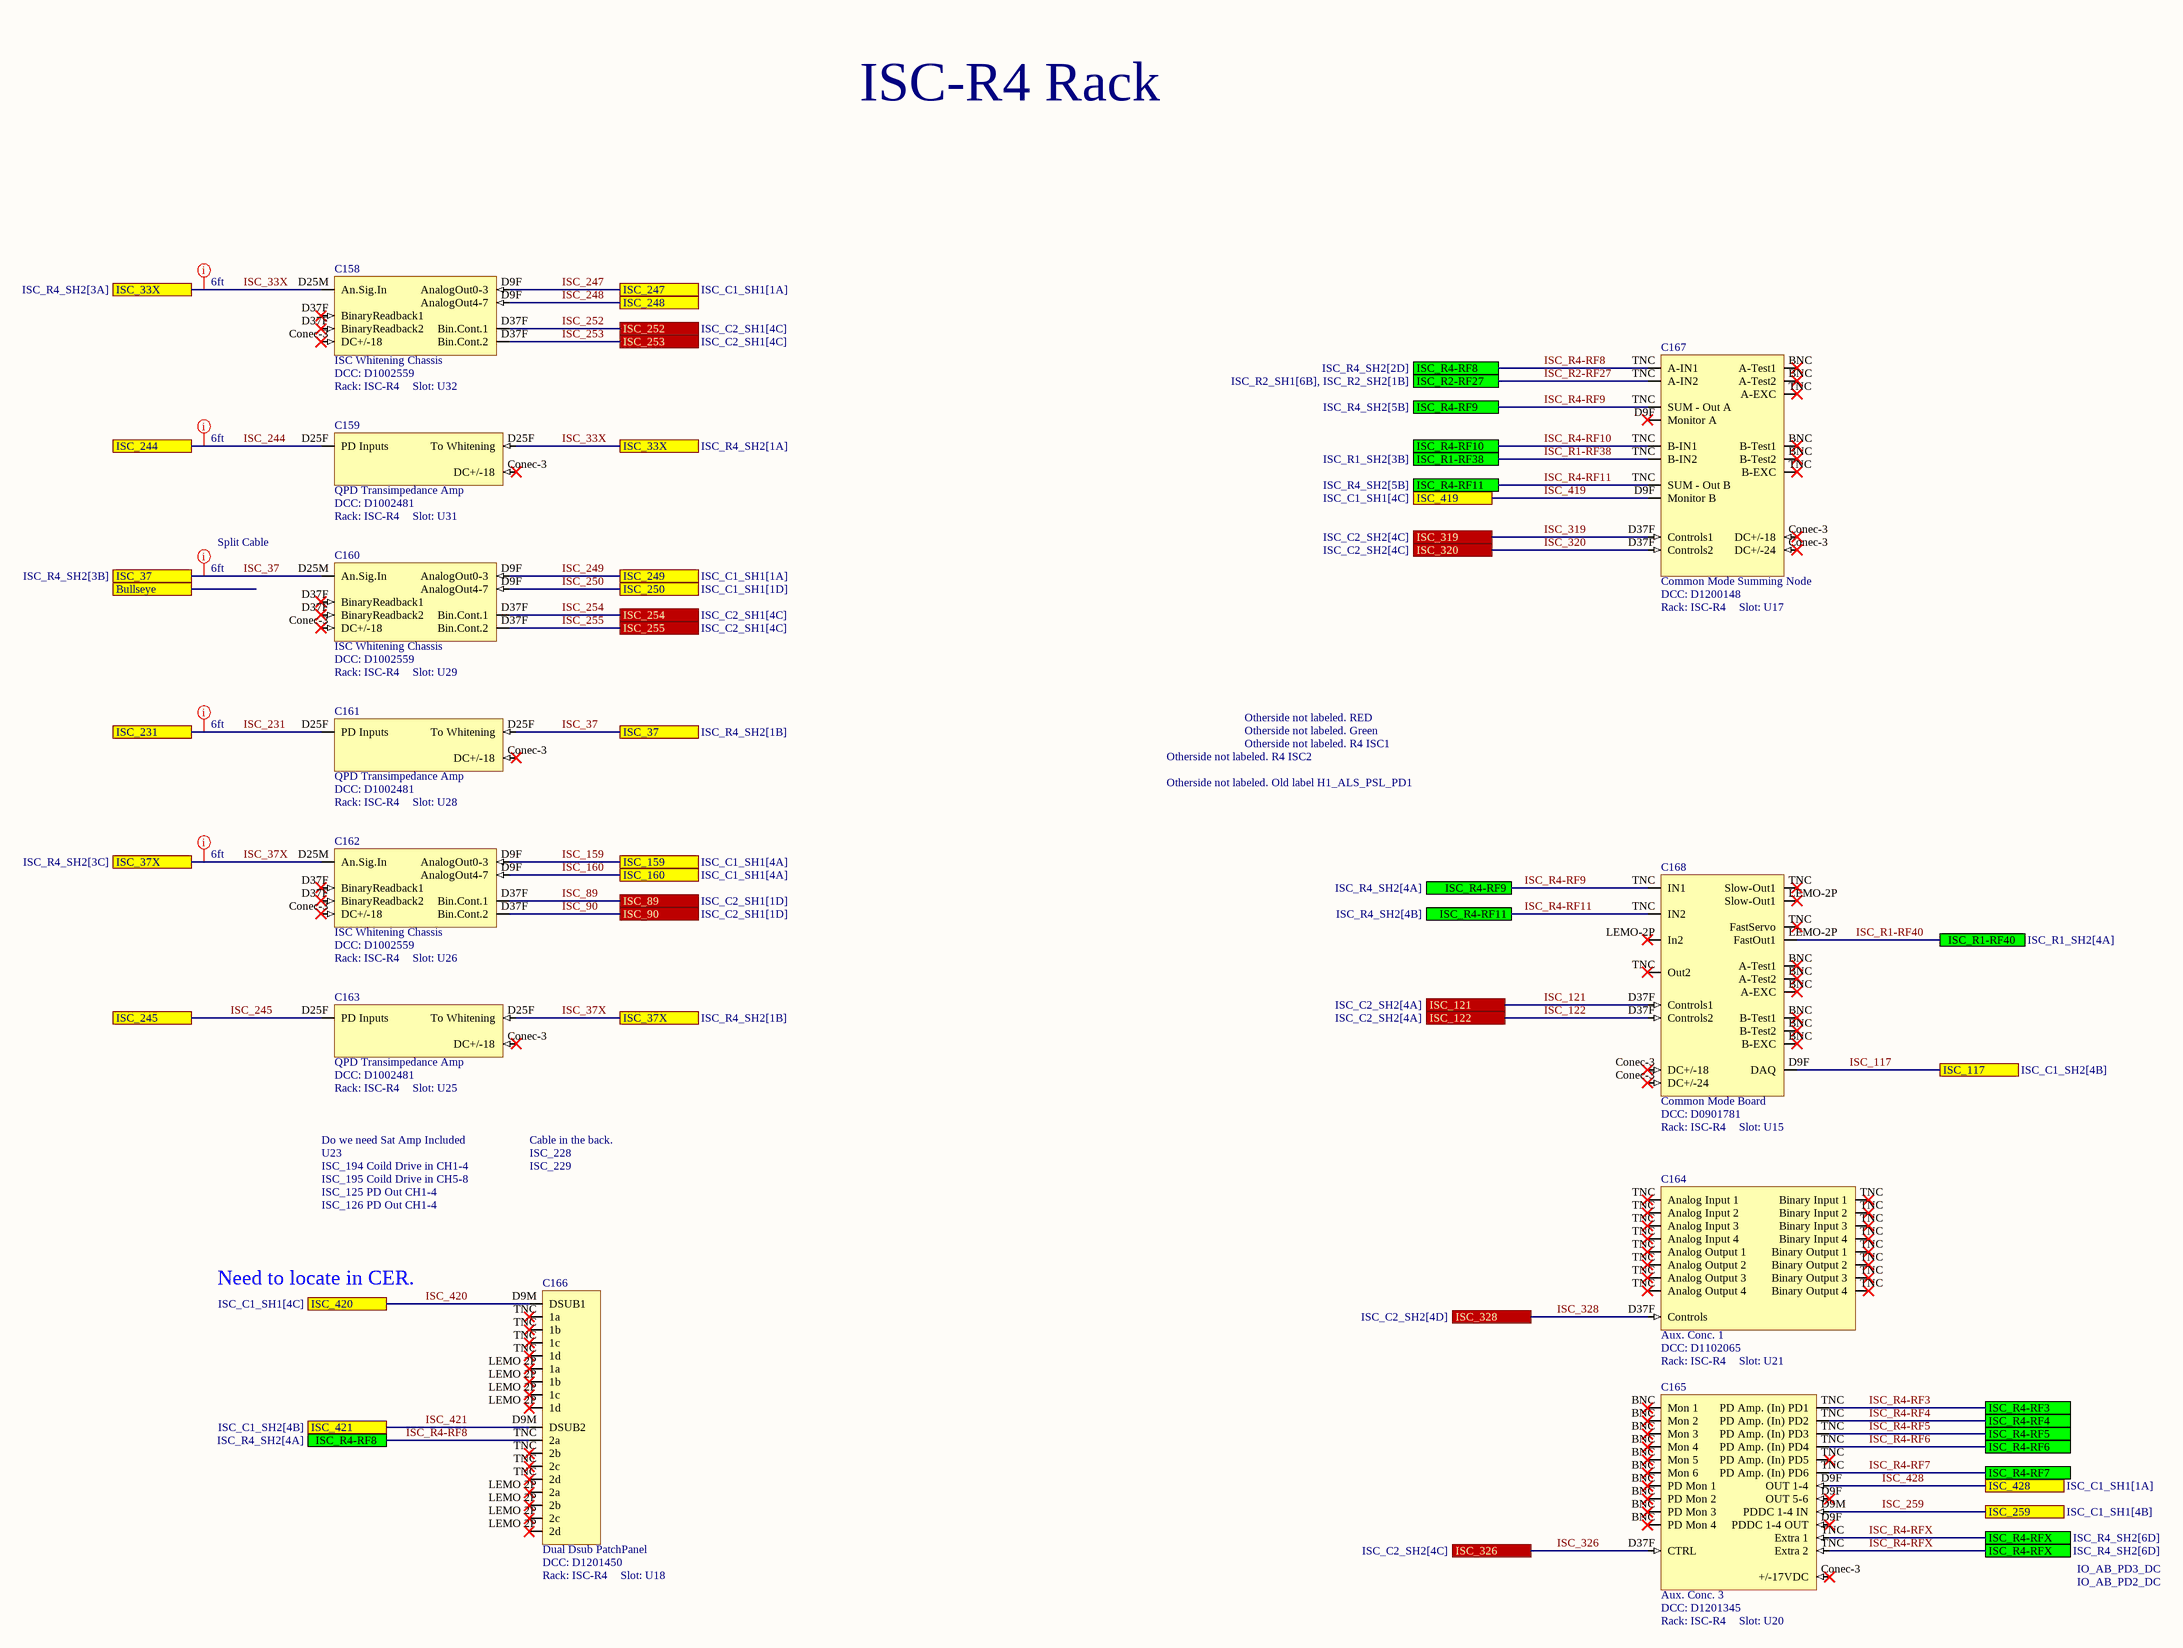
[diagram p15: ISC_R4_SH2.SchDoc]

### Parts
C158  ISC Whitening Chassis  DCC: D1002559  Rack: ISC-R4  Slot: U32
C159  QPD Transimpedance Amp  DCC: D1002481  Rack: ISC-R4  Slot: U31
C160  ISC Whitening Chassis  DCC: D1002559  Rack: ISC-R4  Slot: U29
C161  QPD Transimpedance Amp  DCC: D1002481  Rack: ISC-R4  Slot: U28
C162  ISC Whitening Chassis  DCC: D1002559  Rack: ISC-R4  Slot: U26
C163  QPD Transimpedance Amp  DCC: D1002481  Rack: ISC-R4  Slot: U25
C164  Aux. Conc. 1  DCC: D1102065  Rack: ISC-R4  Slot: U21
C165  Aux. Conc. 3  DCC: D1201345  Rack: ISC-R4  Slot: U20
C166  Dual Dsub PatchPanel  DCC: D1201450  Rack: ISC-R4  Slot: U18
C167  Common Mode Summing Node  DCC: D1200148  Rack: ISC-R4  Slot: U17
C168  Common Mode Board  DCC: D0901781  Rack: ISC-R4  Slot: U15

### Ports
Bullseye, ISC_33X (see ISC_R4_SH2[1A]), ISC_33X (see ISC_R4_SH2[3A]), ISC_37 (see ISC_R4_SH2[1B]), ISC_37 (see ISC_R4_SH2[3B]), ISC_37X (see ISC_R4_SH2[1B]), ISC_37X (see ISC_R4_SH2[3C]), ISC_89 (see ISC_C2_SH1[1D]), ISC_90 (see ISC_C2_SH1[1D]), ISC_117 (see ISC_C1_SH2[4B]), ISC_121 (see ISC_C2_SH2[4A]), ISC_122 (see ISC_C2_SH2[4A]), ISC_159 (see ISC_C1_SH1[4A]), ISC_160 (see ISC_C1_SH1[4A]), ISC_231, ISC_244, ISC_245, ISC_247 (see ISC_C1_SH1[1A]), ISC_248, ISC_249 (see ISC_C1_SH1[1A]), ISC_250 (see ISC_C1_SH1[1D]), ISC_252 (see ISC_C2_SH1[4C]), ISC_253 (see ISC_C2_SH1[4C]), ISC_254 (see ISC_C2_SH1[4C]), ISC_255 (see ISC_C2_SH1[4C]), ISC_259 (see ISC_C1_SH1[4B]), ISC_319 (see ISC_C2_SH2[4C]), ISC_320 (see ISC_C2_SH2[4C]), ISC_326 (see ISC_C2_SH2[4C]), ISC_328 (see ISC_C2_SH2[4D]), ISC_419 (see ISC_C1_SH1[4C]), ISC_420 (see ISC_C1_SH1[4C]), ISC_421 (see ISC_C1_SH2[4B]), ISC_428 (see ISC_C1_SH1[1A]), ISC_R1-RF38 (see ISC_R1_SH2[3B]), ISC_R1-RF40 (see ISC_R1_SH2[4A]), ISC_R2-RF27 (see ISC_R2_SH1[6B], ISC_R2_SH2[1B]), ISC_R4-RF3, ISC_R4-RF4, ISC_R4-RF5, ISC_R4-RF6, ISC_R4-RF7, ISC_R4-RF8 (see ISC_R4_SH2[2D]), ISC_R4-RF8 (see ISC_R4_SH2[4A]), ISC_R4-RF9 (see ISC_R4_SH2[4A]), ISC_R4-RF9 (see ISC_R4_SH2[5B]), ISC_R4-RF10, ISC_R4-RF11 (see ISC_R4_SH2[4B]), ISC_R4-RF11 (see ISC_R4_SH2[5B]), ISC_R4-RFX (see ISC_R4_SH2[6D])

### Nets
ISC_33X: C158.D25M(An.Sig.In) C159.D25F(To_Whitening) ; port ISC_33X
ISC_37: C160.D25M(An.Sig.In) C161.D25F(To_Whitening) ; port ISC_37
ISC_37X: C162.D25M(An.Sig.In) C163.D25F(To_Whitening) ; port ISC_37X
ISC_89: C162.D37F(BinaryReadback1) ; port ISC_89
ISC_90: C162.D37F(Bin.Cont.2) ; port ISC_90
ISC_117: C168.D9F(DAQ) ; port ISC_117
ISC_121: C168.D37F(Controls1) ; port ISC_121
ISC_122: C168.D37F(Controls2) ; port ISC_122
ISC_159: C162.D9F(AnalogOut0-3) ; port ISC_159
ISC_160: C162.D9F(AnalogOut4-7) ; port ISC_160
ISC_231: C161.D25F(PD_Inputs) ; port ISC_231
ISC_244: C159.D25F(PD_Inputs) ; port ISC_244
ISC_245: C163.D25F(PD_Inputs) ; port ISC_245
ISC_247: C158.D9F(AnalogOut0-3) ; port ISC_247
ISC_248: C158.D9F(AnalogOut4-7) ; port ISC_248
ISC_249: C160.D9F(AnalogOut0-3) ; port ISC_249
ISC_250: C160.D9F(AnalogOut4-7) ; port ISC_250
ISC_252: C158.D37F(BinaryReadback1) ; port ISC_252
ISC_253: C158.D37F(Bin.Cont.2) ; port ISC_253
ISC_254: C160.D37F(BinaryReadback1) ; port ISC_254
ISC_255: C160.D37F(Bin.Cont.2) ; port ISC_255
ISC_259: C165.D9M(PDDC_1-4_IN) ; port ISC_259
ISC_319: C167.D37F(Controls1) ; port ISC_319
ISC_320: C167.D37F(Controls2) ; port ISC_320
ISC_326: C165.D37F(CTRL) ; port ISC_326
ISC_328: C164.D37F(Controls) ; port ISC_328
ISC_419: C167.D9F(Monitor_A) ; port ISC_419
ISC_420: C166.D9M(DSUB1) ; port ISC_420
ISC_421: C166.D9M(DSUB2) ; port ISC_421
ISC_428: C165.D9F(PDDC_1-4_OUT) ; port ISC_428
ISC_R1-RF38: C167.TNC(B-IN2) ; port ISC_R1-RF38
ISC_R1-RF40: C168.LEMO-2P(In2) ; port ISC_R1-RF40
ISC_R2-RF27: C167.TNC(A-IN2) ; port ISC_R2-RF27
ISC_R4-RF3: C165.TNC(PD_Amp._(In)_PD1) ; port ISC_R4-RF3
ISC_R4-RF4: C165.TNC(PD_Amp._(In)_PD2) ; port ISC_R4-RF4
ISC_R4-RF5: C165.TNC(PD_Amp._(In)_PD3) ; port ISC_R4-RF5
ISC_R4-RF6: C165.TNC(PD_Amp._(In)_PD4) ; port ISC_R4-RF6
ISC_R4-RF7: C165.TNC(PD_Amp._(In)_PD6) ; port ISC_R4-RF7
ISC_R4-RF8: C166.TNC(1a) C167.TNC(A-IN1) ; port ISC_R4-RF8
ISC_R4-RF9: C167.TNC(SUM_-_Out_A) C168.TNC(IN1) ; port ISC_R4-RF9
ISC_R4-RF10: C167.TNC(B-IN1) ; port ISC_R4-RF10
ISC_R4-RF11: C167.TNC(SUM_-_Out_B) C168.TNC(IN2) ; port ISC_R4-RF11
ISC_R4-RFX: C165.TNC(Extra_1) ; port ISC_R4-RFX

Not connected (* = marked no-connect by the designer): C158 Conec-3(DC+/-18)*; C159 Conec-3(DC+/-18)*; C160 Conec-3(DC+/-18)*; C161 Conec-3(DC+/-18)*; C162 Conec-3(DC+/-18)*; C163 Conec-3(DC+/-18)*; C164 TNC(Analog_Input_1)*; C165 BNC(PD_Mon_1)* Conec-3(+/-17VDC)*; C166 LEMO 2P(1a)*; C167 BNC(A-Test1)* Conec-3(DC+/-18)*; C168 BNC(A-Test1)* Conec-3(DC+/-18)*

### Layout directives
Length: 6ft: ISC_33X, ISC_37, ISC_37X, ISC_231, ISC_244

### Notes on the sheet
- ISC-R4 Rack
- Split Cable
- Otherside not labeled. R4 ISC2
- Otherside not labeled. RED
- Otherside not labeled. Green
- Otherside not labeled. R4 ISC1
- Otherside not labeled. Old label H1_ALS_PSL_PD1
- Do we need Sat Amp Included
- U23
- Cable in the back.
- ISC_228
- ISC_194 Coild Drive in CH1-4
- ISC_195 Coild Drive in CH5-8
- ISC_125 PD Out CH1-4
- ISC_126 PD Out CH1-4
- ISC_229
- Need to locate in CER.
- IO_AB_PD3_DC
- IO_AB_PD2_DC

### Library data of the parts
C158 C160 C162 = ISC Whitening: Serial: Sxxxxxxx
C159 C161 C163 = QPD Transimpedance Amp: Serial: Sxxxxxxx; System: ISC
C164 = Aux. Conc. 1: Serial: Sxxxxxxx; System: ISC
C165 = Aux. Conc. 3: Serial: Sxxxxxxx; System: ISC
C166 = Dual Dsub PatchPanel: Serial: Sxxxxxxx; System: ISC
C167 = Common Mode Summing Node: Serial: Sxxxxxxx; System: ISC
C168 = CommonModeBoard: Serial: Sxxxxxxx; System: ISC

## Sheet ISC_R3_SH1.SchDoc: ISC System Wiring Diagram
size B; DrawnBy: Filiberto Clara; Engineer: Filiberto Clara; Organization: LIGO Laboratory; Address1: California Institute of Technology; Address2: Massachusetts Institute of Technology; DocumentNumber: D1900511; Revision: V11; SheetNumber: 17; SheetTotal: 39
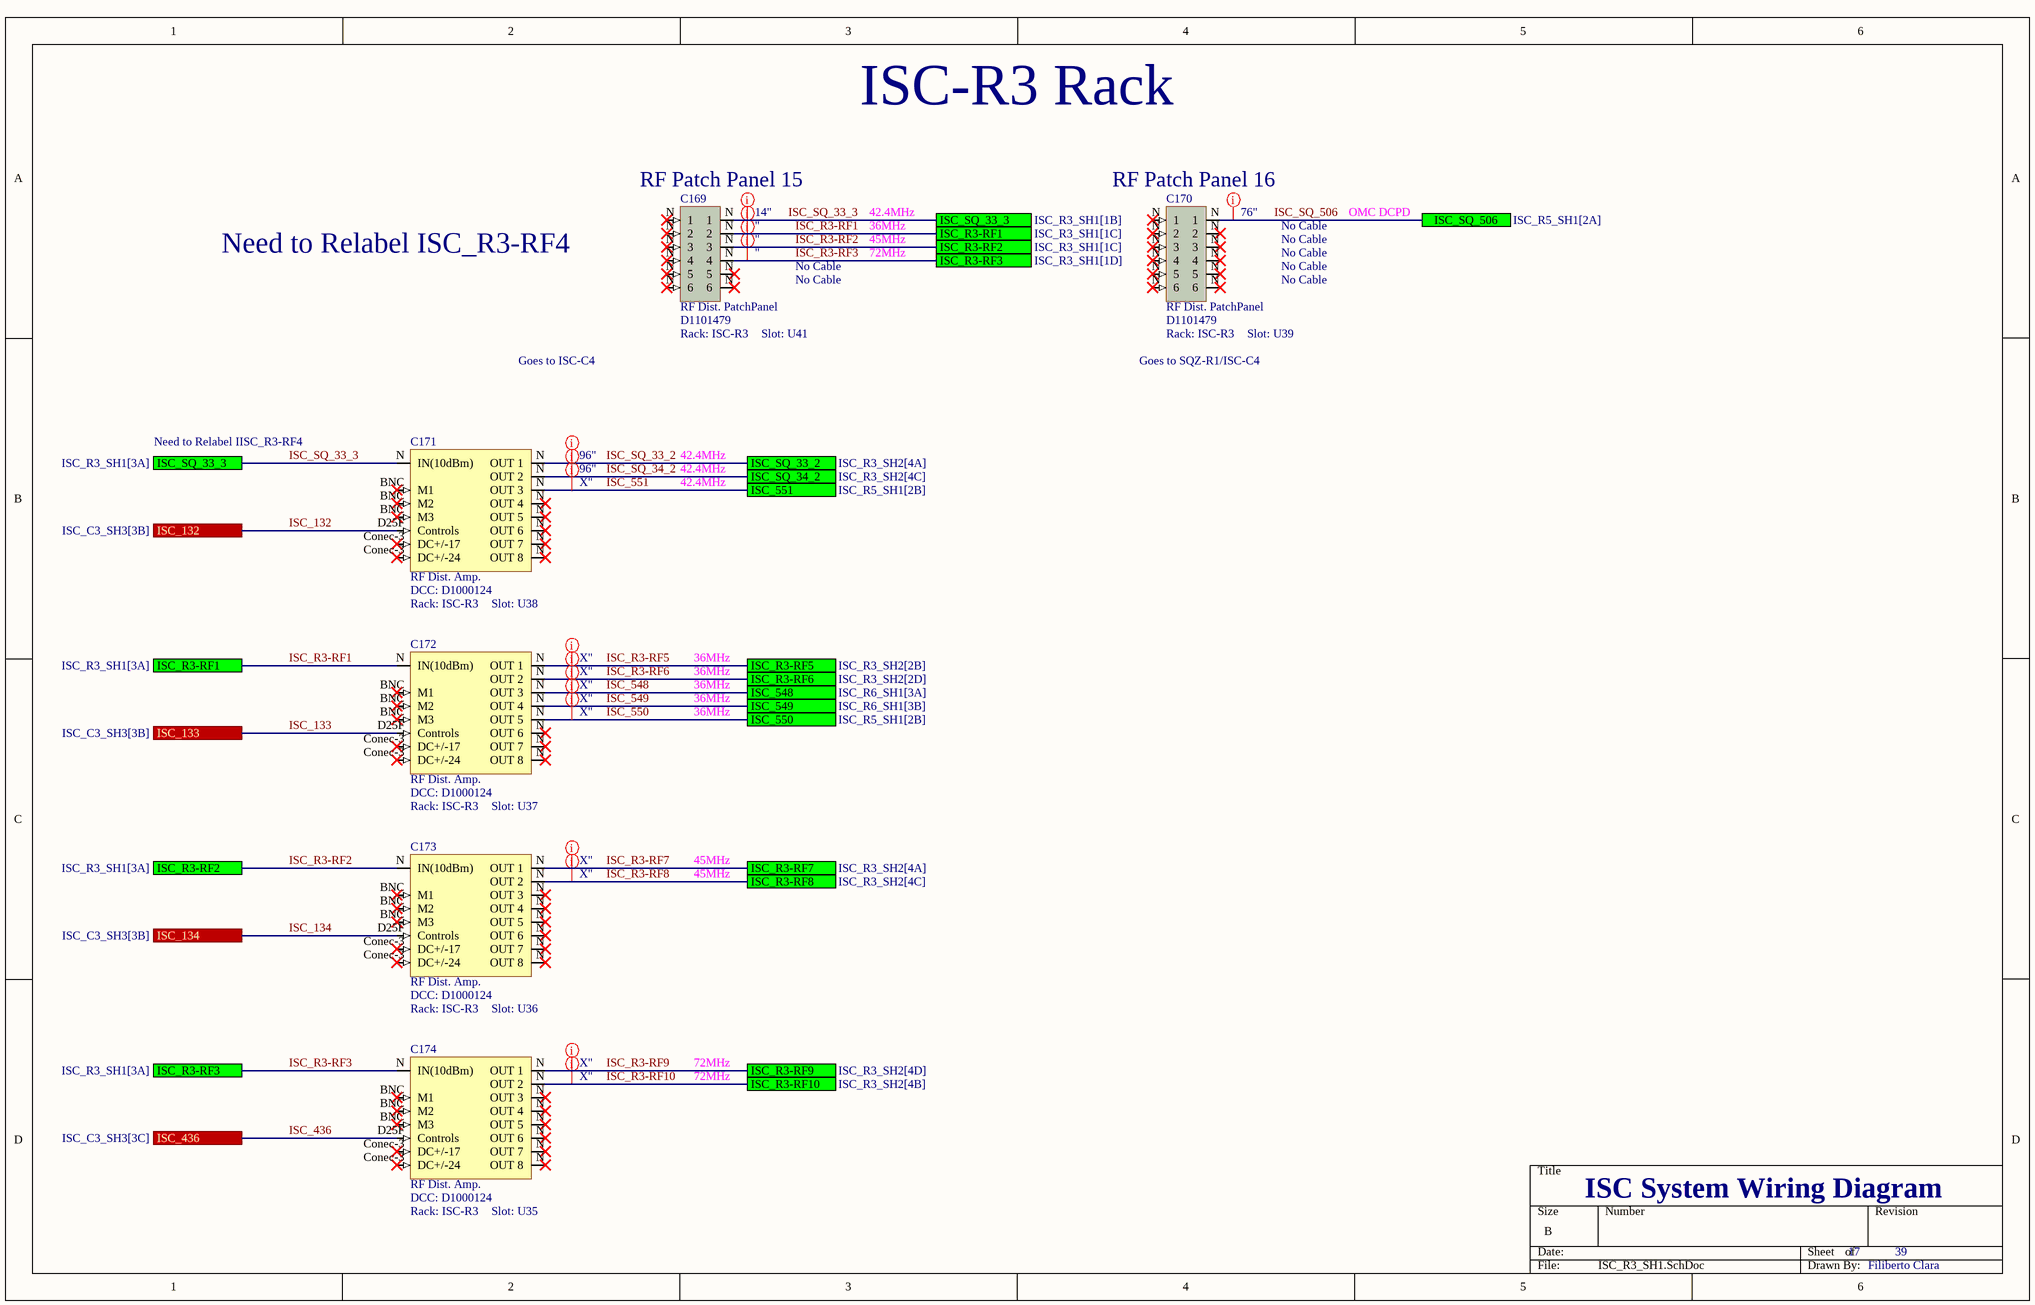
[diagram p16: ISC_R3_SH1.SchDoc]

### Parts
C169  RF Dist. PatchPanel  DCC: D1101479  Rack: ISC-R3  Slot: U41
C170  RF Dist. PatchPanel  DCC: D1101479  Rack: ISC-R3  Slot: U39
C171  RF Dist. Amp.  DCC: D1000124  Rack: ISC-R3  Slot: U38
C172  RF Dist. Amp.  DCC: D1000124  Rack: ISC-R3  Slot: U37
C173  RF Dist. Amp.  DCC: D1000124  Rack: ISC-R3  Slot: U36
C174  RF Dist. Amp.  DCC: D1000124  Rack: ISC-R3  Slot: U35

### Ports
ISC_132 (see ISC_C3_SH3[3B]), ISC_133 (see ISC_C3_SH3[3B]), ISC_134 (see ISC_C3_SH3[3B]), ISC_436 (see ISC_C3_SH3[3C]), ISC_548 (see ISC_R6_SH1[3A]), ISC_549 (see ISC_R6_SH1[3B]), ISC_550 (see ISC_R5_SH1[2B]), ISC_551 (see ISC_R5_SH1[2B]), ISC_R3-RF1 (see ISC_R3_SH1[1C]), ISC_R3-RF1 (see ISC_R3_SH1[3A]), ISC_R3-RF2 (see ISC_R3_SH1[1C]), ISC_R3-RF2 (see ISC_R3_SH1[3A]), ISC_R3-RF3 (see ISC_R3_SH1[1D]), ISC_R3-RF3 (see ISC_R3_SH1[3A]), ISC_R3-RF5 (see ISC_R3_SH2[2B]), ISC_R3-RF6 (see ISC_R3_SH2[2D]), ISC_R3-RF7 (see ISC_R3_SH2[4A]), ISC_R3-RF8 (see ISC_R3_SH2[4C]), ISC_R3-RF9 (see ISC_R3_SH2[4D]), ISC_R3-RF10 (see ISC_R3_SH2[4B]), ISC_SQ_33_2 (see ISC_R3_SH2[4A]), ISC_SQ_33_3 (see ISC_R3_SH1[1B]), ISC_SQ_33_3 (see ISC_R3_SH1[3A]), ISC_SQ_34_2 (see ISC_R3_SH2[4C]), ISC_SQ_506 (see ISC_R5_SH1[2A])

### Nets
ISC_132: C171.D25F(Controls) ; port ISC_132
ISC_133: C172.D25F(Controls) ; port ISC_133
ISC_134: C173.D25F(Controls) ; port ISC_134
ISC_436: C174.D25F(Controls) ; port ISC_436
ISC_548: C172.N(OUT_3) ; port ISC_548
ISC_549: C172.N(OUT_4) ; port ISC_549
ISC_550: C172.N(OUT_5) ; port ISC_550
ISC_551: C171.N(OUT_3) ; port ISC_551
ISC_R3-RF1: C169.N(2) C172.N(IN(10dBm)) ; port ISC_R3-RF1
ISC_R3-RF2: C169.N(3) C173.N(IN(10dBm)) ; port ISC_R3-RF2
ISC_R3-RF3: C169.N(4) C174.N(IN(10dBm)) ; port ISC_R3-RF3
ISC_R3-RF5: C172.N(OUT_1) ; port ISC_R3-RF5
ISC_R3-RF6: C172.N(OUT_2) ; port ISC_R3-RF6
ISC_R3-RF7: C173.N(OUT_1) ; port ISC_R3-RF7
ISC_R3-RF8: C173.N(OUT_2) ; port ISC_R3-RF8
ISC_R3-RF9: C174.N(OUT_1) ; port ISC_R3-RF9
ISC_R3-RF10: C174.N(OUT_2) ; port ISC_R3-RF10
ISC_SQ_33_2: C171.N(OUT_1) ; port ISC_SQ_33_2
ISC_SQ_33_3: C169.N(1) C171.N(IN(10dBm)) ; port ISC_SQ_33_3
ISC_SQ_34_2: C171.N(OUT_2) ; port ISC_SQ_34_2
ISC_SQ_506: C170.N(1) ; port ISC_SQ_506

Not connected (* = marked no-connect by the designer): C171 BNC(M1)* Conec-3(DC+/-17)*; C172 BNC(M1)* Conec-3(DC+/-17)*; C173 BNC(M1)* Conec-3(DC+/-17)*; C174 BNC(M1)* Conec-3(DC+/-17)*

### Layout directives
Length: ": ISC_R3-RF1, ISC_R3-RF2, ISC_R3-RF3
Length: 96": ISC_SQ_33_2, ISC_SQ_34_2
Length: X": ISC_548, ISC_549, ISC_550, ISC_551, ISC_R3-RF5, ISC_R3-RF6, ISC_R3-RF7, ISC_R3-RF8, ISC_R3-RF9, ISC_R3-RF10
Length: 14": ISC_SQ_33_3
Length: 76": ISC_SQ_506

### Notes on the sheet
- ISC-R3 Rack
- (near C169) RF Patch Panel 15
- 36MHz
- 45MHz
- 42.4MHz
- (near C170) RF Patch Panel 16
- No Cable
- OMC DCPD
- Need to Relabel ISC_R3-RF4
- 72MHz
- Goes to ISC-C4
- Goes to SQZ-R1/ISC-C4
- Need to Relabel IISC_R3-RF4

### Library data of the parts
C169 C170 = RF Dist. PatchPanel: Serial: Sxxxxxxx; System: ISC
C171-C174 = RF Distribution Amplifier: Serial: Sxxxxxxx; System: ISC

## Sheet ISC_R3_SH2.SchDoc: ISC System Wiring Diagram
size C; DrawnBy: Filiberto Clara; Engineer: Filiberto Clara; Organization: LIGO Laboratory; Address1: California Institute of Technology; Address2: Massachusetts Institute of Technology; DocumentNumber: D1900511; Revision: V11; SheetNumber: 18; SheetTotal: 39
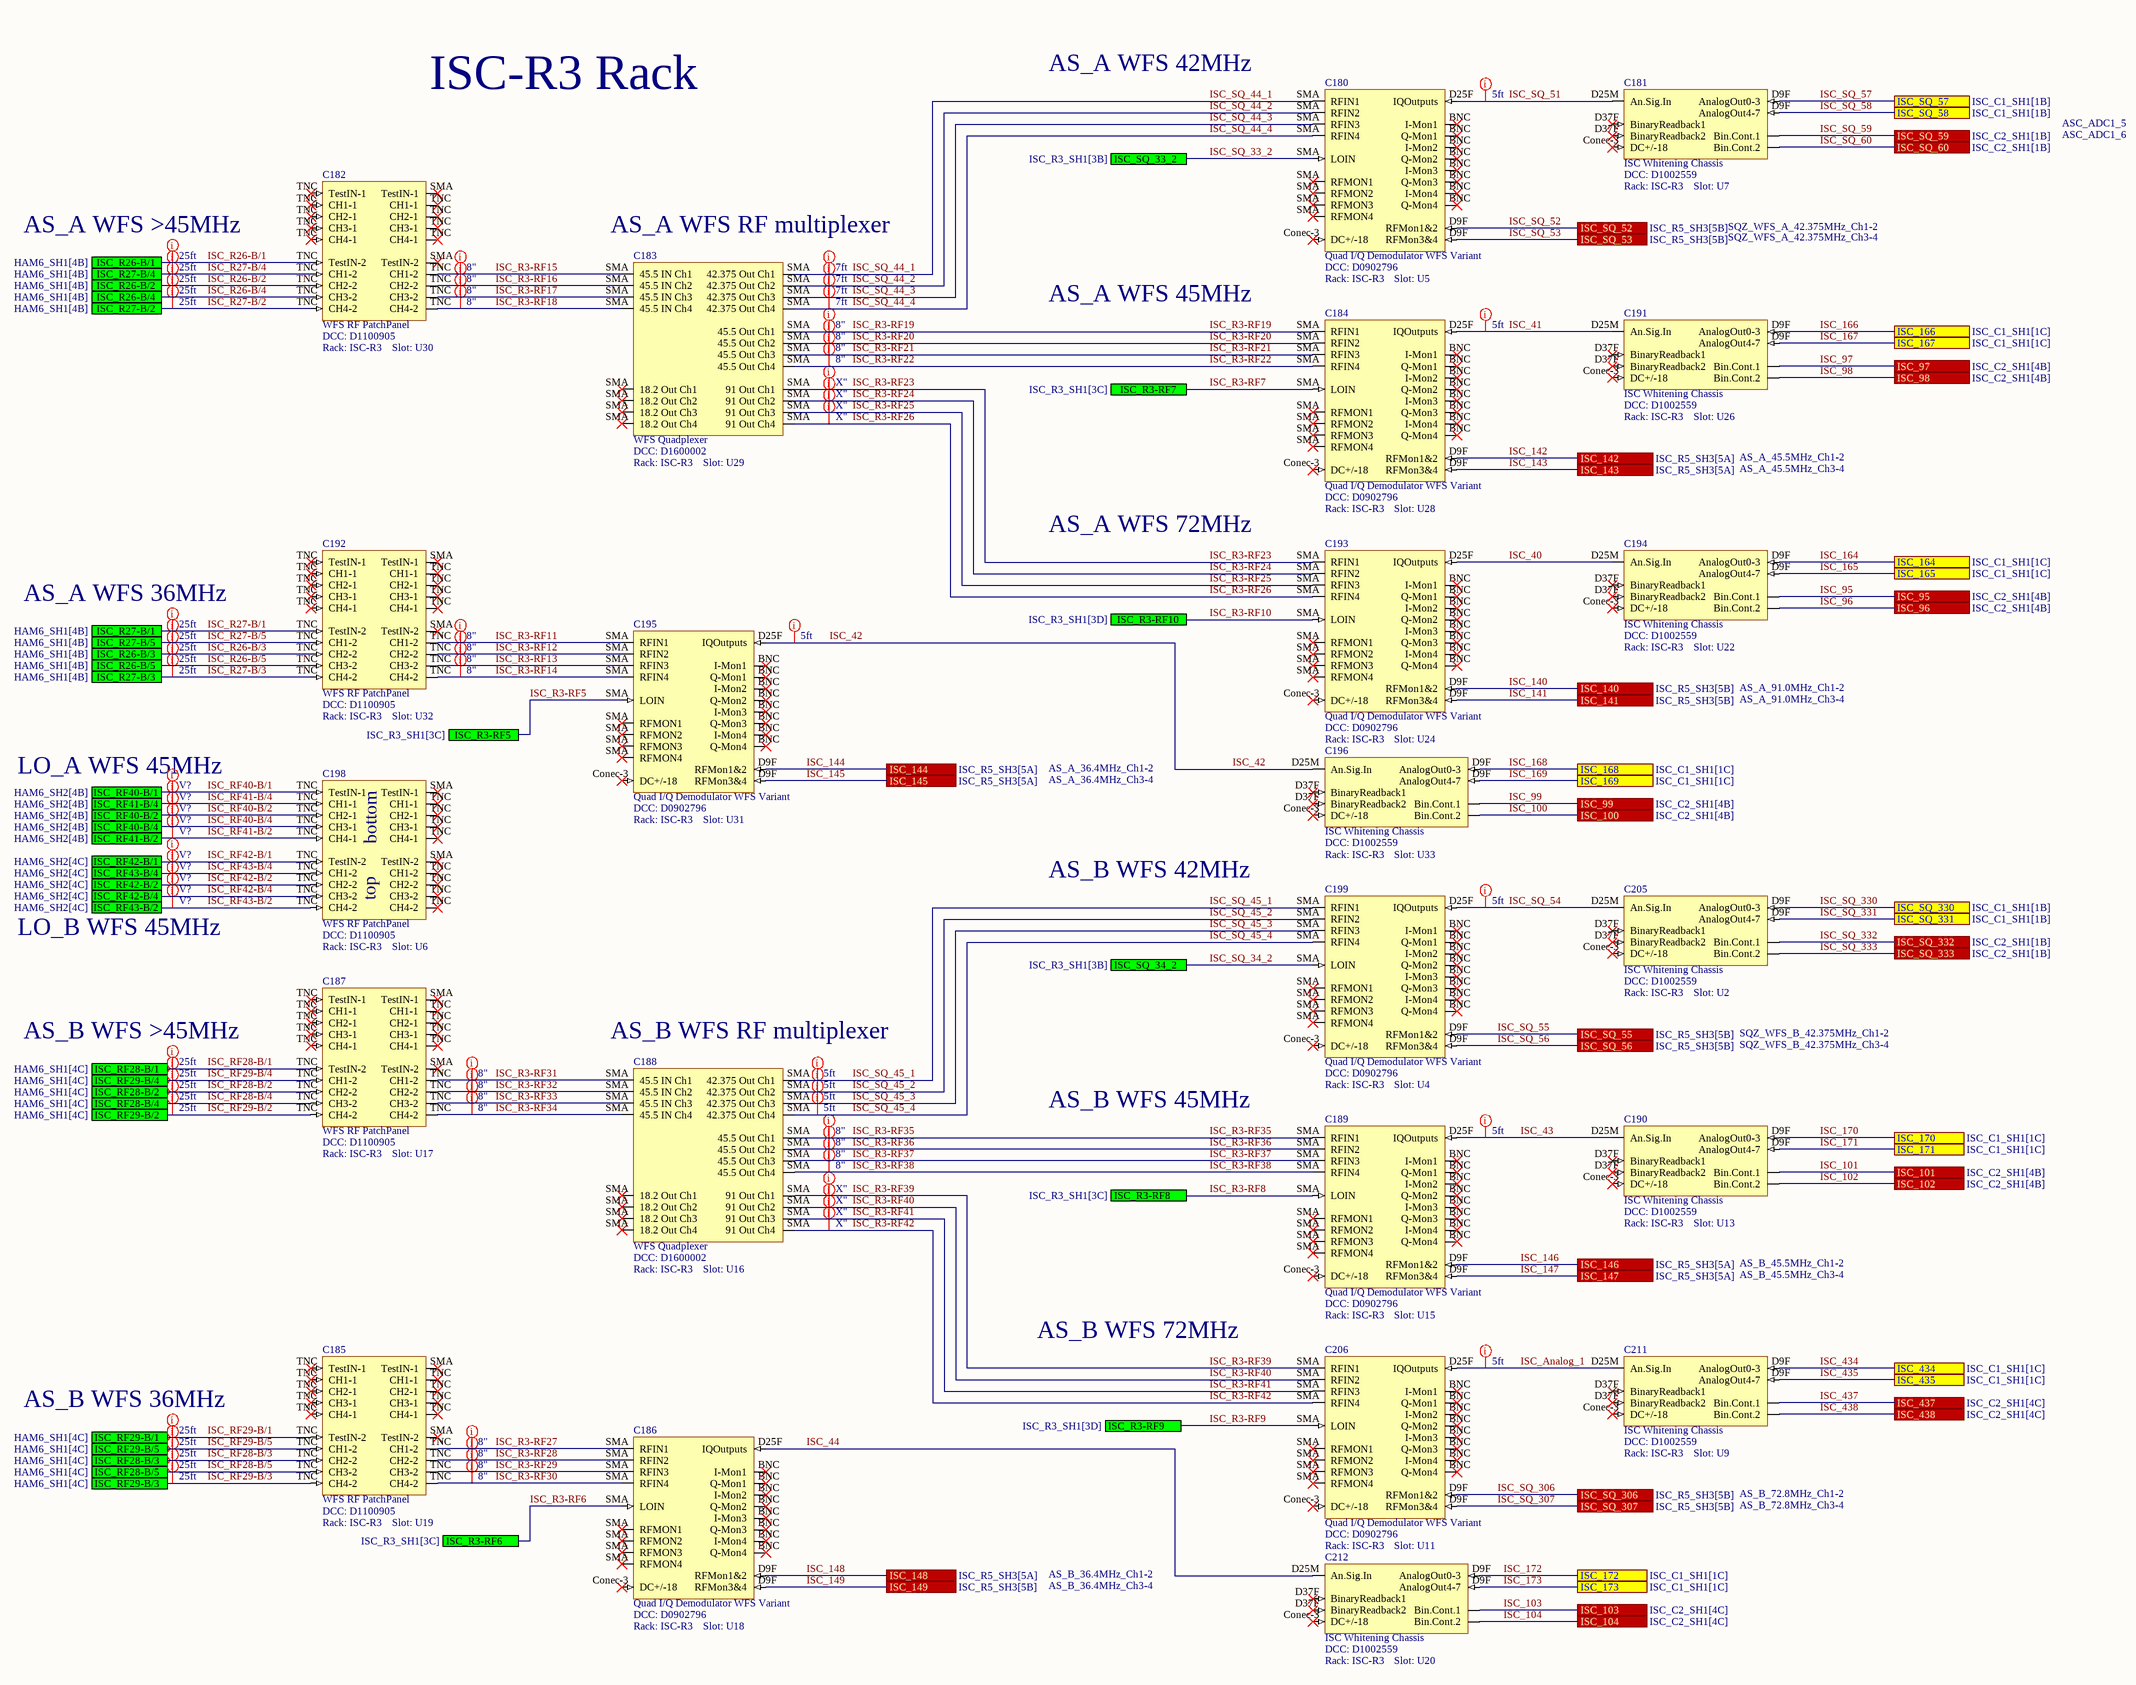
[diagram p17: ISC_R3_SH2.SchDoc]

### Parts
C180  Quad I/Q Demodulator WFS Variant  DCC: D0902796  Rack: ISC-R3  Slot: U5
C181  ISC Whitening Chassis  DCC: D1002559  Rack: ISC-R3  Slot: U7
C182  WFS RF PatchPanel  DCC: D1100905  Rack: ISC-R3  Slot: U30
C183  WFS Quadplexer  DCC: D1600002  Rack: ISC-R3  Slot: U29
C184  Quad I/Q Demodulator WFS Variant  DCC: D0902796  Rack: ISC-R3  Slot: U28
C185  WFS RF PatchPanel  DCC: D1100905  Rack: ISC-R3  Slot: U19
C186  Quad I/Q Demodulator WFS Variant  DCC: D0902796  Rack: ISC-R3  Slot: U18
C187  WFS RF PatchPanel  DCC: D1100905  Rack: ISC-R3  Slot: U17
C188  WFS Quadplexer  DCC: D1600002  Rack: ISC-R3  Slot: U16
C189  Quad I/Q Demodulator WFS Variant  DCC: D0902796  Rack: ISC-R3  Slot: U15
C190  ISC Whitening Chassis  DCC: D1002559  Rack: ISC-R3  Slot: U13
C191  ISC Whitening Chassis  DCC: D1002559  Rack: ISC-R3  Slot: U26
C192  WFS RF PatchPanel  DCC: D1100905  Rack: ISC-R3  Slot: U32
C193  Quad I/Q Demodulator WFS Variant  DCC: D0902796  Rack: ISC-R3  Slot: U24
C194  ISC Whitening Chassis  DCC: D1002559  Rack: ISC-R3  Slot: U22
C195  Quad I/Q Demodulator WFS Variant  DCC: D0902796  Rack: ISC-R3  Slot: U31
C196  ISC Whitening Chassis  DCC: D1002559  Rack: ISC-R3  Slot: U33
C198  WFS RF PatchPanel  DCC: D1100905  Rack: ISC-R3  Slot: U6
C199  Quad I/Q Demodulator WFS Variant  DCC: D0902796  Rack: ISC-R3  Slot: U4
C205  ISC Whitening Chassis  DCC: D1002559  Rack: ISC-R3  Slot: U2
C206  Quad I/Q Demodulator WFS Variant  DCC: D0902796  Rack: ISC-R3  Slot: U11
C211  ISC Whitening Chassis  DCC: D1002559  Rack: ISC-R3  Slot: U9
C212  ISC Whitening Chassis  DCC: D1002559  Rack: ISC-R3  Slot: U20

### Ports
ISC_95 (see ISC_C2_SH1[4B]), ISC_96 (see ISC_C2_SH1[4B]), ISC_97 (see ISC_C2_SH1[4B]), ISC_98 (see ISC_C2_SH1[4B]), ISC_99 (see ISC_C2_SH1[4B]), ISC_100 (see ISC_C2_SH1[4B]), ISC_101 (see ISC_C2_SH1[4B]), ISC_102 (see ISC_C2_SH1[4B]), ISC_103 (see ISC_C2_SH1[4C]), ISC_104 (see ISC_C2_SH1[4C]), ISC_140 (see ISC_R5_SH3[5B]), ISC_141 (see ISC_R5_SH3[5B]), ISC_142 (see ISC_R5_SH3[5A]), ISC_143 (see ISC_R5_SH3[5A]), ISC_144 (see ISC_R5_SH3[5A]), ISC_145 (see ISC_R5_SH3[5A]), ISC_146 (see ISC_R5_SH3[5A]), ISC_147 (see ISC_R5_SH3[5A]), ISC_148 (see ISC_R5_SH3[5A]), ISC_149 (see ISC_R5_SH3[5B]), ISC_164 (see ISC_C1_SH1[1C]), ISC_165 (see ISC_C1_SH1[1C]), ISC_166 (see ISC_C1_SH1[1C]), ISC_167 (see ISC_C1_SH1[1C]), ISC_168 (see ISC_C1_SH1[1C]), ISC_169 (see ISC_C1_SH1[1C]), ISC_170 (see ISC_C1_SH1[1C]), ISC_171 (see ISC_C1_SH1[1C]), ISC_172 (see ISC_C1_SH1[1C]), ISC_173 (see ISC_C1_SH1[1C]), ISC_434 (see ISC_C1_SH1[1C]), ISC_435 (see ISC_C1_SH1[1C]), ISC_437 (see ISC_C2_SH1[4C]), ISC_438 (see ISC_C2_SH1[4C]), ISC_R3-RF5 (see ISC_R3_SH1[3C]), ISC_R3-RF6 (see ISC_R3_SH1[3C]), ISC_R3-RF7 (see ISC_R3_SH1[3C]), ISC_R3-RF8 (see ISC_R3_SH1[3C]), ISC_R3-RF9 (see ISC_R3_SH1[3D]), ISC_R3-RF10 (see ISC_R3_SH1[3D]), ISC_R26-B/1 (see HAM6_SH1[4B]), ISC_R26-B/2 (see HAM6_SH1[4B]), ISC_R26-B/3 (see HAM6_SH1[4B]), ISC_R26-B/4 (see HAM6_SH1[4B]), ISC_R26-B/5 (see HAM6_SH1[4B]), ISC_R27-B/1 (see HAM6_SH1[4B]), ISC_R27-B/2 (see HAM6_SH1[4B]), ISC_R27-B/3 (see HAM6_SH1[4B]), ISC_R27-B/4 (see HAM6_SH1[4B]), ISC_R27-B/5 (see HAM6_SH1[4B]), ISC_RF28-B/1 (see HAM6_SH1[4C]), ISC_RF28-B/2 (see HAM6_SH1[4C]), ISC_RF28-B/3 (see HAM6_SH1[4C]), ISC_RF28-B/4 (see HAM6_SH1[4C]), ISC_RF28-B/5 (see HAM6_SH1[4C]), ISC_RF29-B/1 (see HAM6_SH1[4C]), ISC_RF29-B/2 (see HAM6_SH1[4C]), ISC_RF29-B/3 (see HAM6_SH1[4C]), ISC_RF29-B/4 (see HAM6_SH1[4C]), ISC_RF29-B/5 (see HAM6_SH1[4C]), ISC_RF40-B/1 (see HAM6_SH2[4B]), ISC_RF40-B/2 (see HAM6_SH2[4B]), ISC_RF40-B/4 (see HAM6_SH2[4B]), ISC_RF41-B/2 (see HAM6_SH2[4B]), ISC_RF41-B/4 (see HAM6_SH2[4B]), ISC_RF42-B/1 (see HAM6_SH2[4C]), ISC_RF42-B/2 (see HAM6_SH2[4C]), ISC_RF42-B/4 (see HAM6_SH2[4C]), ISC_RF43-B/2 (see HAM6_SH2[4C]), ISC_RF43-B/4 (see HAM6_SH2[4C]), ISC_SQ_33_2 (see ISC_R3_SH1[3B]), ISC_SQ_34_2 (see ISC_R3_SH1[3B]), ISC_SQ_52 (see ISC_R5_SH3[5B]), ISC_SQ_53 (see ISC_R5_SH3[5B]), ISC_SQ_55 (see ISC_R5_SH3[5B]), ISC_SQ_56 (see ISC_R5_SH3[5B]), ISC_SQ_57 (see ISC_C1_SH1[1B]), ISC_SQ_58 (see ISC_C1_SH1[1B]), ISC_SQ_59 (see ISC_C2_SH1[1B]), ISC_SQ_60 (see ISC_C2_SH1[1B]), ISC_SQ_306 (see ISC_R5_SH3[5B]), ISC_SQ_307 (see ISC_R5_SH3[5B]), ISC_SQ_330 (see ISC_C1_SH1[1B]), ISC_SQ_331 (see ISC_C1_SH1[1B]), ISC_SQ_332 (see ISC_C2_SH1[1B]), ISC_SQ_333 (see ISC_C2_SH1[1B])

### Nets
ISC_40: C193.D25F(IQOutputs) C194.D25M(An.Sig.In)
ISC_41: C184.D25F(IQOutputs) C191.D25M(An.Sig.In)
ISC_42: C195.D25F(IQOutputs) C196.D25M(An.Sig.In)
ISC_43: C189.D25F(IQOutputs) C190.D25M(An.Sig.In)
ISC_44: C186.D25F(IQOutputs) C212.D25M(An.Sig.In)
ISC_95: C194.D37F(BinaryReadback1) ; port ISC_95
ISC_96: C194.D37F(Bin.Cont.2) ; port ISC_96
ISC_97: C191.D37F(BinaryReadback1) ; port ISC_97
ISC_98: C191.D37F(Bin.Cont.2) ; port ISC_98
ISC_99: C196.D37F(BinaryReadback1) ; port ISC_99
ISC_100: C196.D37F(Bin.Cont.2) ; port ISC_100
ISC_101: C190.D37F(BinaryReadback1) ; port ISC_101
ISC_102: C190.D37F(Bin.Cont.2) ; port ISC_102
ISC_103: C212.D37F(BinaryReadback1) ; port ISC_103
ISC_104: C212.D37F(Bin.Cont.2) ; port ISC_104
ISC_140: C193.D9F(RFMon1&2) ; port ISC_140
ISC_141: C193.D9F(RFMon3&4) ; port ISC_141
ISC_142: C184.D9F(RFMon1&2) ; port ISC_142
ISC_143: C184.D9F(RFMon3&4) ; port ISC_143
ISC_144: C195.D9F(RFMon1&2) ; port ISC_144
ISC_145: C195.D9F(RFMon3&4) ; port ISC_145
ISC_146: C189.D9F(RFMon1&2) ; port ISC_146
ISC_147: C189.D9F(RFMon3&4) ; port ISC_147
ISC_148: C186.D9F(RFMon1&2) ; port ISC_148
ISC_149: C186.D9F(RFMon3&4) ; port ISC_149
ISC_164: C194.D9F(AnalogOut0-3) ; port ISC_164
ISC_165: C194.D9F(AnalogOut4-7) ; port ISC_165
ISC_166: C191.D9F(AnalogOut0-3) ; port ISC_166
ISC_167: C191.D9F(AnalogOut4-7) ; port ISC_167
ISC_168: C196.D9F(AnalogOut0-3) ; port ISC_168
ISC_169: C196.D9F(AnalogOut4-7) ; port ISC_169
ISC_170: C190.D9F(AnalogOut0-3) ; port ISC_170
ISC_171: C190.D9F(AnalogOut4-7) ; port ISC_171
ISC_172: C212.D9F(AnalogOut0-3) ; port ISC_172
ISC_173: C212.D9F(AnalogOut4-7) ; port ISC_173
ISC_434: C211.D9F(AnalogOut0-3) ; port ISC_434
ISC_435: C211.D9F(AnalogOut4-7) ; port ISC_435
ISC_437: C211.D37F(BinaryReadback1) ; port ISC_437
ISC_438: C211.D37F(Bin.Cont.2) ; port ISC_438
ISC_Analog_1: C206.D25F(IQOutputs) C211.D25M(An.Sig.In)
ISC_R3-RF5: C195.SMA(LOIN) ; port ISC_R3-RF5
ISC_R3-RF6: C186.SMA(LOIN) ; port ISC_R3-RF6
ISC_R3-RF7: C184.SMA(LOIN) ; port ISC_R3-RF7
ISC_R3-RF8: C189.SMA(LOIN) ; port ISC_R3-RF8
ISC_R3-RF9: C206.SMA(LOIN) ; port ISC_R3-RF9
ISC_R3-RF10: C193.SMA(LOIN) ; port ISC_R3-RF10
ISC_R3-RF11: C192.TNC(CH1-2) C195.SMA(RFIN1)
ISC_R3-RF12: C192.TNC(CH2-2) C195.SMA(RFIN2)
ISC_R3-RF13: C192.TNC(CH3-2) C195.SMA(RFIN3)
ISC_R3-RF14: C192.TNC(CH4-2) C195.SMA(RFIN4)
ISC_R3-RF15: C182.TNC(CH1-2) C183.SMA(45.5_IN_Ch1)
ISC_R3-RF16: C182.TNC(CH2-2) C183.SMA(45.5_IN_Ch2)
ISC_R3-RF17: C182.TNC(CH3-2) C183.SMA(45.5_IN_Ch3)
ISC_R3-RF18: C182.TNC(CH4-2) C183.SMA(45.5_IN_Ch4)
ISC_R3-RF19: C183.SMA(45.5_Out_Ch1) C184.SMA(RFIN1)
ISC_R3-RF20: C183.SMA(45.5_Out_Ch2) C184.SMA(RFIN2)
ISC_R3-RF21: C183.SMA(45.5_Out_Ch3) C184.SMA(RFIN3)
ISC_R3-RF22: C183.SMA(45.5_Out_Ch4) C184.SMA(RFIN4)
ISC_R3-RF23: C183.SMA(91_Out_Ch1) C193.SMA(RFIN1)
ISC_R3-RF24: C183.SMA(91_Out_Ch2) C193.SMA(RFIN2)
ISC_R3-RF25: C183.SMA(91_Out_Ch3) C193.SMA(RFIN3)
ISC_R3-RF26: C183.SMA(91_Out_Ch4) C193.SMA(RFIN4)
ISC_R3-RF27: C185.TNC(CH1-2) C186.SMA(RFIN1)
ISC_R3-RF28: C185.TNC(CH2-2) C186.SMA(RFIN2)
ISC_R3-RF29: C185.TNC(CH3-2) C186.SMA(RFIN3)
ISC_R3-RF30: C185.TNC(CH4-2) C186.SMA(RFIN4)
ISC_R3-RF31: C187.TNC(CH1-2) C188.SMA(45.5_IN_Ch1)
ISC_R3-RF32: C187.TNC(CH2-2) C188.SMA(45.5_IN_Ch2)
ISC_R3-RF33: C187.TNC(CH3-2) C188.SMA(45.5_IN_Ch3)
ISC_R3-RF34: C187.TNC(CH4-2) C188.SMA(45.5_IN_Ch4)
ISC_R3-RF35: C188.SMA(45.5_Out_Ch1) C189.SMA(RFIN1)
ISC_R3-RF36: C188.SMA(45.5_Out_Ch2) C189.SMA(RFIN2)
ISC_R3-RF37: C188.SMA(45.5_Out_Ch3) C189.SMA(RFIN3)
ISC_R3-RF38: C188.SMA(45.5_Out_Ch4) C189.SMA(RFIN4)
ISC_R3-RF39: C188.SMA(91_Out_Ch1) C206.SMA(RFIN1)
ISC_R3-RF40: C188.SMA(91_Out_Ch2) C206.SMA(RFIN2)
ISC_R3-RF41: C188.SMA(91_Out_Ch3) C206.SMA(RFIN3)
ISC_R3-RF42: C188.SMA(91_Out_Ch4) C206.SMA(RFIN4)
ISC_R26-B/1: C182.TNC(TestIN-1) ; port ISC_R26-B/1
ISC_R26-B/2: C182.TNC(CH2-2) ; port ISC_R26-B/2
ISC_R26-B/3: C192.TNC(CH2-2) ; port ISC_R26-B/3
ISC_R26-B/4: C182.TNC(CH3-2) ; port ISC_R26-B/4
ISC_R26-B/5: C192.TNC(CH3-2) ; port ISC_R26-B/5
ISC_R27-B/1: C192.TNC(TestIN-1) ; port ISC_R27-B/1
ISC_R27-B/2: C182.TNC(CH4-2) ; port ISC_R27-B/2
ISC_R27-B/3: C192.TNC(CH4-2) ; port ISC_R27-B/3
ISC_R27-B/4: C182.TNC(CH1-2) ; port ISC_R27-B/4
ISC_R27-B/5: C192.TNC(CH1-2) ; port ISC_R27-B/5
ISC_RF28-B/1: C187.TNC(TestIN-1) ; port ISC_RF28-B/1
ISC_RF28-B/2: C187.TNC(CH2-2) ; port ISC_RF28-B/2
ISC_RF28-B/3: C185.TNC(CH2-2) ; port ISC_RF28-B/3
ISC_RF28-B/4: C187.TNC(CH3-2) ; port ISC_RF28-B/4
ISC_RF28-B/5: C185.TNC(CH3-2) ; port ISC_RF28-B/5
ISC_RF29-B/1: C185.TNC(TestIN-1) ; port ISC_RF29-B/1
ISC_RF29-B/2: C187.TNC(CH4-2) ; port ISC_RF29-B/2
ISC_RF29-B/3: C185.TNC(CH4-2) ; port ISC_RF29-B/3
ISC_RF29-B/4: C187.TNC(CH1-2) ; port ISC_RF29-B/4
ISC_RF29-B/5: C185.TNC(CH1-2) ; port ISC_RF29-B/5
ISC_RF40-B/1: C198.TNC(TestIN-1) ; port ISC_RF40-B/1
ISC_RF40-B/2: C198.TNC(CH2-1) ; port ISC_RF40-B/2
ISC_RF40-B/4: C198.TNC(CH3-1) ; port ISC_RF40-B/4
ISC_RF41-B/2: C198.TNC(CH4-1) ; port ISC_RF41-B/2
ISC_RF41-B/4: C198.TNC(CH1-1) ; port ISC_RF41-B/4
ISC_RF42-B/1: C198.TNC(TestIN-2) ; port ISC_RF42-B/1
ISC_RF42-B/2: C198.TNC(CH2-2) ; port ISC_RF42-B/2
ISC_RF42-B/4: C198.TNC(CH3-2) ; port ISC_RF42-B/4
ISC_RF43-B/2: C198.TNC(CH4-2) ; port ISC_RF43-B/2
ISC_RF43-B/4: C198.TNC(CH1-2) ; port ISC_RF43-B/4
ISC_SQ_33_2: C180.SMA(LOIN) ; port ISC_SQ_33_2
ISC_SQ_34_2: C199.SMA(LOIN) ; port ISC_SQ_34_2
ISC_SQ_44_1: C180.SMA(RFIN1) C183.SMA(42.375_Out_Ch1)
ISC_SQ_44_2: C180.SMA(RFIN2) C183.SMA(42.375_Out_Ch2)
ISC_SQ_44_3: C180.SMA(RFIN3) C183.SMA(42.375_Out_Ch3)
ISC_SQ_44_4: C180.SMA(RFIN4) C183.SMA(42.375_Out_Ch4)
ISC_SQ_45_1: C188.SMA(42.375_Out_Ch1) C199.SMA(RFIN1)
ISC_SQ_45_2: C188.SMA(42.375_Out_Ch2) C199.SMA(RFIN2)
ISC_SQ_45_3: C188.SMA(42.375_Out_Ch3) C199.SMA(RFIN3)
ISC_SQ_45_4: C188.SMA(42.375_Out_Ch4) C199.SMA(RFIN4)
ISC_SQ_51: C180.D25F(IQOutputs) C181.D25M(An.Sig.In)
ISC_SQ_52: C180.D9F(RFMon1&2) ; port ISC_SQ_52
ISC_SQ_53: C180.D9F(RFMon3&4) ; port ISC_SQ_53
ISC_SQ_54: C199.D25F(IQOutputs) C205.D25M(An.Sig.In)
ISC_SQ_55: C199.D9F(RFMon1&2) ; port ISC_SQ_55
ISC_SQ_56: C199.D9F(RFMon3&4) ; port ISC_SQ_56
ISC_SQ_57: C181.D9F(AnalogOut0-3) ; port ISC_SQ_57
ISC_SQ_58: C181.D9F(AnalogOut4-7) ; port ISC_SQ_58
ISC_SQ_59: C181.D37F(BinaryReadback1) ; port ISC_SQ_59
ISC_SQ_60: C181.D37F(Bin.Cont.2) ; port ISC_SQ_60
ISC_SQ_306: C206.D9F(RFMon1&2) ; port ISC_SQ_306
ISC_SQ_307: C206.D9F(RFMon3&4) ; port ISC_SQ_307
ISC_SQ_330: C205.D9F(AnalogOut0-3) ; port ISC_SQ_330
ISC_SQ_331: C205.D9F(AnalogOut4-7) ; port ISC_SQ_331
ISC_SQ_332: C205.D37F(BinaryReadback1) ; port ISC_SQ_332
ISC_SQ_333: C205.D37F(Bin.Cont.2) ; port ISC_SQ_333

Not connected (* = marked no-connect by the designer): C180 BNC(I-Mon1)* Conec-3(DC+/-18)*; C181 Conec-3(DC+/-18)*; C182 SMA(TestIN-1)*; C184 BNC(I-Mon1)* Conec-3(DC+/-18)*; C185 SMA(TestIN-1)*; C186 BNC(I-Mon1)* Conec-3(DC+/-18)*; C187 SMA(TestIN-1)*; C189 BNC(I-Mon1)* Conec-3(DC+/-18)*; C190 Conec-3(DC+/-18)*; C191 Conec-3(DC+/-18)*; C192 SMA(TestIN-1)*; C193 BNC(I-Mon1)* Conec-3(DC+/-18)*; C194 Conec-3(DC+/-18)*; C195 BNC(I-Mon1)* Conec-3(DC+/-18)*; C196 Conec-3(DC+/-18)*; C198 SMA(TestIN-1)*; C199 BNC(I-Mon1)* Conec-3(DC+/-18)*; C205 Conec-3(DC+/-18)*; C206 BNC(I-Mon1)* Conec-3(DC+/-18)*; C211 Conec-3(DC+/-18)*; C212 Conec-3(DC+/-18)*

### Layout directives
Length: 5ft: ISC_41, ISC_42, ISC_43, ISC_Analog_1, ISC_SQ_45_1, ISC_SQ_45_2, ISC_SQ_45_3, ISC_SQ_45_4, ISC_SQ_51, ISC_SQ_54
Length: 8": ISC_R3-RF11, ISC_R3-RF12, ISC_R3-RF13, ISC_R3-RF14, ISC_R3-RF15, ISC_R3-RF16, ISC_R3-RF17, ISC_R3-RF18, ISC_R3-RF19, ISC_R3-RF20, ISC_R3-RF21, ISC_R3-RF22, ISC_R3-RF27, ISC_R3-RF28, ISC_R3-RF29, ISC_R3-RF30, ISC_R3-RF31, ISC_R3-RF32, ISC_R3-RF33, ISC_R3-RF34, ISC_R3-RF35, ISC_R3-RF36, ISC_R3-RF37, ISC_R3-RF38
Length: 25ft: ISC_R26-B/1, ISC_R26-B/2, ISC_R26-B/3, ISC_R26-B/4, ISC_R26-B/5, ISC_R27-B/1, ISC_R27-B/2, ISC_R27-B/3, ISC_R27-B/4, ISC_R27-B/5, ISC_RF28-B/1, ISC_RF28-B/2, ISC_RF28-B/3, ISC_RF28-B/4, ISC_RF28-B/5, ISC_RF29-B/1, ISC_RF29-B/2, ISC_RF29-B/3, ISC_RF29-B/4, ISC_RF29-B/5
Length: X": ISC_R3-RF23, ISC_R3-RF24, ISC_R3-RF25, ISC_R3-RF26, ISC_R3-RF39, ISC_R3-RF40, ISC_R3-RF41, ISC_R3-RF42
Length: 7ft: ISC_SQ_44_1, ISC_SQ_44_2, ISC_SQ_44_3, ISC_SQ_44_4
Length: V?: ISC_RF40-B/1, ISC_RF40-B/2, ISC_RF40-B/4, ISC_RF41-B/2, ISC_RF41-B/4, ISC_RF42-B/1, ISC_RF42-B/2, ISC_RF42-B/4, ISC_RF43-B/2, ISC_RF43-B/4

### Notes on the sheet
- ISC-R3 Rack
- AS_A WFS 42MHz
- ASC_ADC1_5
- ASC_ADC1_6
- AS_A WFS >45MHz
- (near C183) AS_A WFS RF multiplexer
- SQZ_WFS_A_42.375MHz_Ch1-2
- SQZ_WFS_A_42.375MHz_Ch3-4
- AS_A WFS 45MHz
- AS_A_45.5MHz_Ch1-2
- AS_A_45.5MHz_Ch3-4
- AS_A WFS 72MHz
- AS_A WFS 36MHz
- AS_A_91.0MHz_Ch1-2
- AS_A_91.0MHz_Ch3-4
- LO_A WFS 45MHz
- AS_A_36.4MHz_Ch1-2
- AS_A_36.4MHz_Ch3-4
- (near C198) bottom
- AS_B WFS 42MHz
- LO_B WFS 45MHz
- (near C198) top
- AS_B WFS >45MHz
- (near C188) AS_B WFS RF multiplexer
- SQZ_WFS_B_42.375MHz_Ch1-2
- SQZ_WFS_B_42.375MHz_Ch3-4
- AS_B WFS 45MHz
- AS_B_45.5MHz_Ch1-2
- AS_B_45.5MHz_Ch3-4
- AS_B WFS 72MHz
- AS_B WFS 36MHz
- AS_B_72.8MHz_Ch1-2
- AS_B_72.8MHz_Ch3-4
- AS_B_36.4MHz_Ch1-2
- AS_B_36.4MHz_Ch3-4

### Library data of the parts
C180 C184 C186 C189 C193 C195 C199 C206 = QuadIQdemod_WFS: Serial: Sxxxxxxx; System: ISC
C181 C190 C191 C194 C196 C205 C211 C212 = ISC Whitening: Serial: Sxxxxxxx
C182 C185 C187 C192 C198 = WFS RFPD PatchPanel: Serial: Sxxxxxxx; System: ISC
C183 C188 = WFS Quadplexer: Serial: Sxxxxxxx; System: ISC

## Sheet ISC_R5_SH1.SchDoc: ISC System Wiring Diagram
size B; DrawnBy: Filiberto Clara; Engineer: Filiberto Clara; Organization: LIGO Laboratory; Address1: California Institute of Technology; Address2: Massachusetts Institute of Technology; DocumentNumber: D1900511; Revision: V11; SheetNumber: 19; SheetTotal: 39
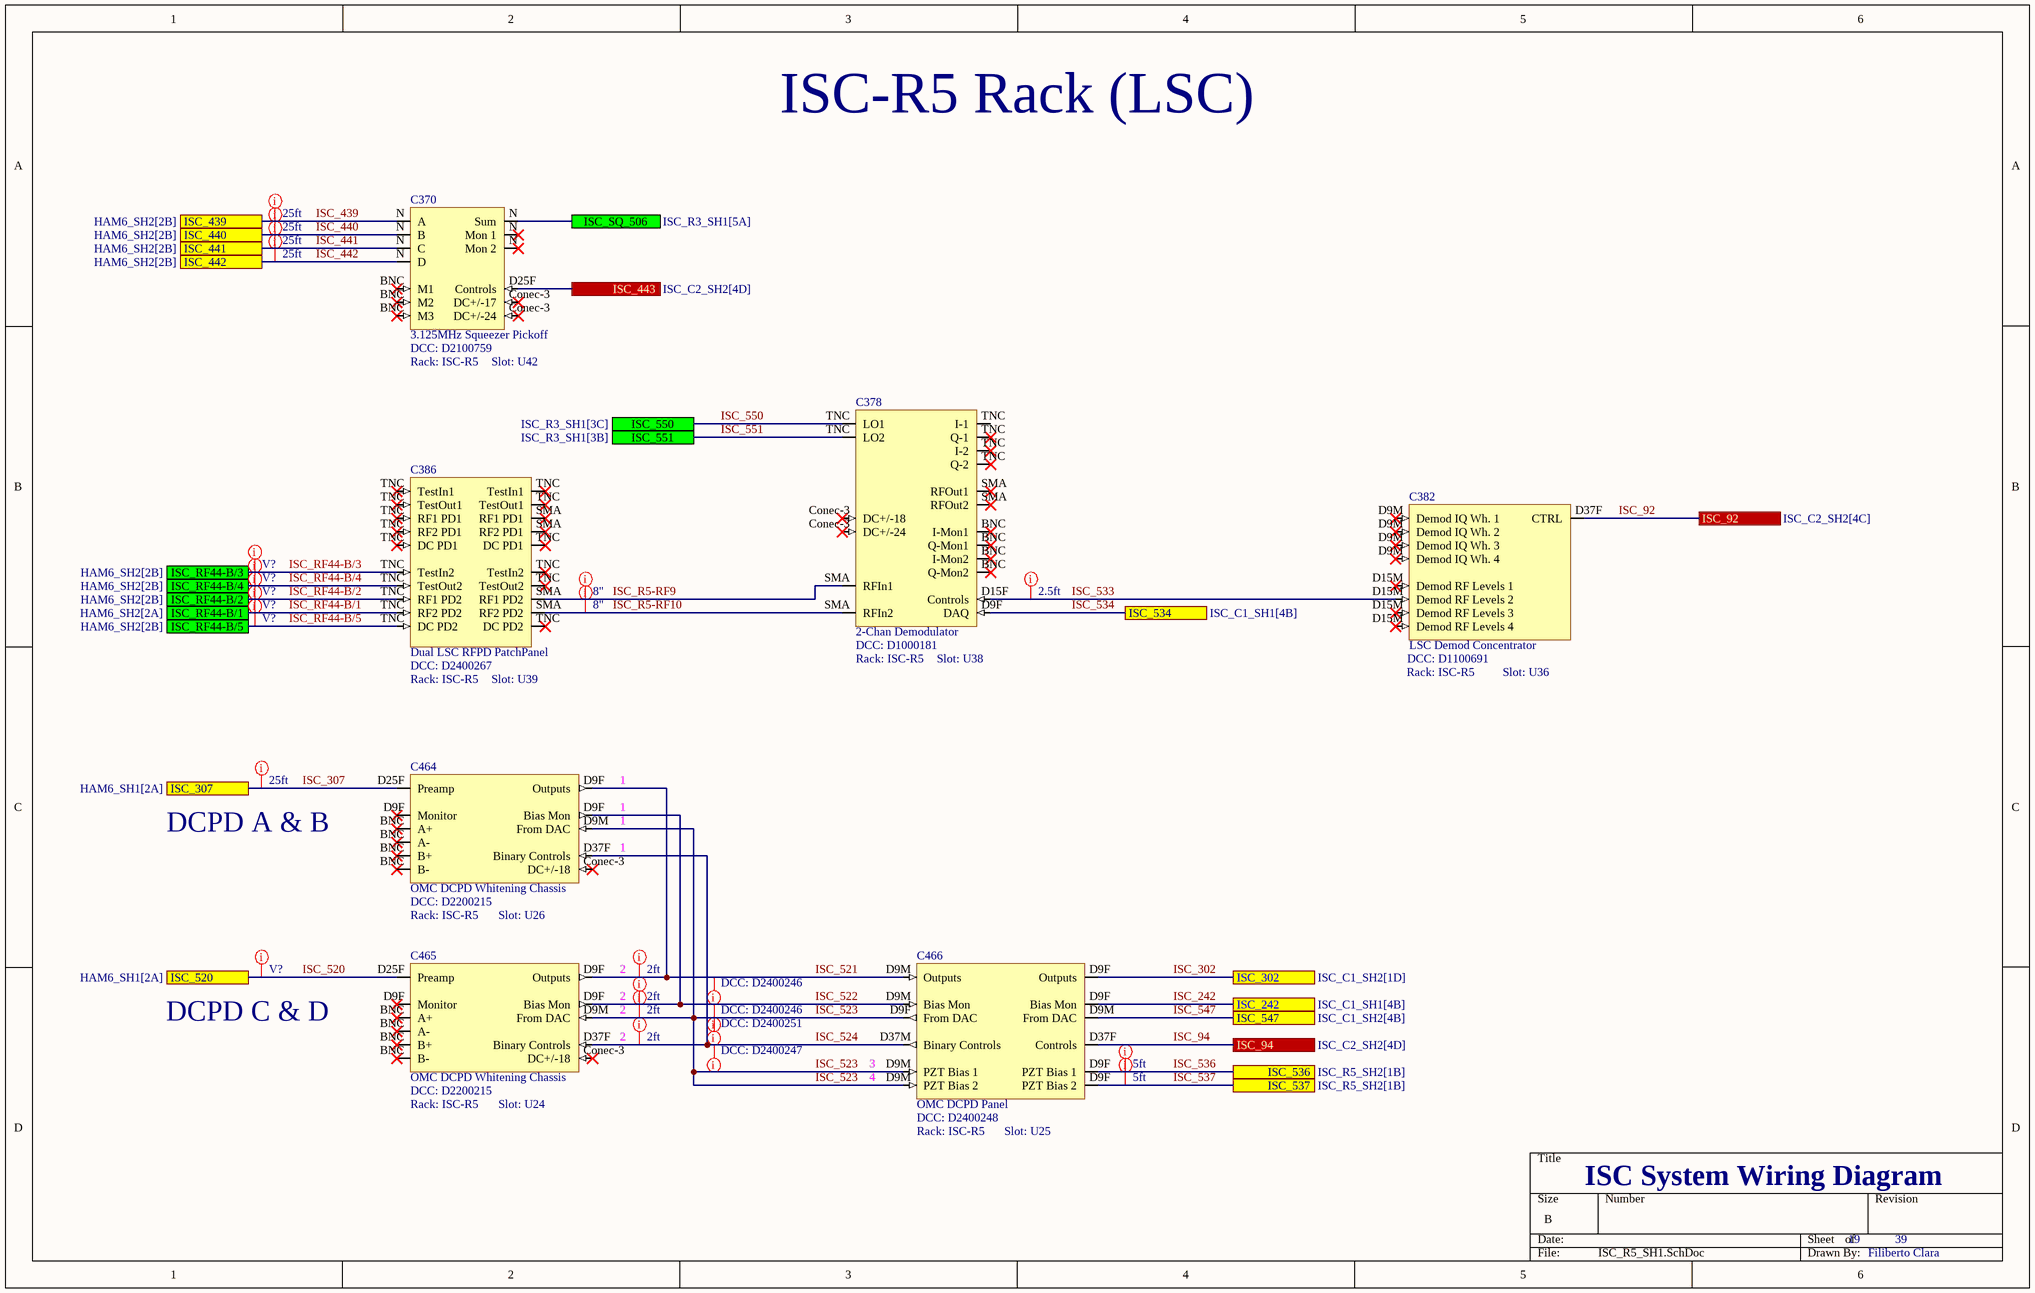
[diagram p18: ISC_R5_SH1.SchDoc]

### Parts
C370  3.125MHz Squeezer Pickoff  DCC: D2100759  Rack: ISC-R5  Slot: U42
C378  2-Chan Demodulator  DCC: D1000181  Rack: ISC-R5  Slot: U38
C382  LSC Demod Concentrator  DCC: D1100691  Rack: ISC-R5  Slot: U36
C386  Dual LSC RFPD PatchPanel  DCC: D2400267  Rack: ISC-R5  Slot: U39
C464  OMC DCPD Whitening Chassis  DCC: D2200215  Rack: ISC-R5  Slot: U26
C465  OMC DCPD Whitening Chassis  DCC: D2200215  Rack: ISC-R5  Slot: U24
C466  OMC DCPD Panel  DCC: D2400248  Rack: ISC-R5  Slot: U25

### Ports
ISC_92 (see ISC_C2_SH2[4C]), ISC_94 (see ISC_C2_SH2[4D]), ISC_242 (see ISC_C1_SH1[4B]), ISC_302 (see ISC_C1_SH2[1D]), ISC_307 (see HAM6_SH1[2A]), ISC_439 (see HAM6_SH2[2B]), ISC_440 (see HAM6_SH2[2B]), ISC_441 (see HAM6_SH2[2B]), ISC_442 (see HAM6_SH2[2B]), ISC_443 (see ISC_C2_SH2[4D]), ISC_520 (see HAM6_SH1[2A]), ISC_534 (see ISC_C1_SH1[4B]), ISC_536 (see ISC_R5_SH2[1B]), ISC_537 (see ISC_R5_SH2[1B]), ISC_547 (see ISC_C1_SH2[4B]), ISC_550 (see ISC_R3_SH1[3C]), ISC_551 (see ISC_R3_SH1[3B]), ISC_RF44-B/1 (see HAM6_SH2[2A]), ISC_RF44-B/2 (see HAM6_SH2[2B]), ISC_RF44-B/3 (see HAM6_SH2[2B]), ISC_RF44-B/4 (see HAM6_SH2[2B]), ISC_RF44-B/5 (see HAM6_SH2[2B]), ISC_SQ_506 (see ISC_R3_SH1[5A])

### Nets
ISC_92: C382.D37F(CTRL) ; port ISC_92
ISC_94: C466.D37F(Controls) ; port ISC_94
ISC_242: C466.D9F(Bias_Mon) ; port ISC_242
ISC_302: C466.D9F(Outputs) ; port ISC_302
ISC_307: C464.D25F(Preamp) ; port ISC_307
ISC_439: C370.N(A) ; port ISC_439
ISC_440: C370.N(B) ; port ISC_440
ISC_441: C370.N(C) ; port ISC_441
ISC_442: C370.N(D) ; port ISC_442
ISC_443: C370.D25F(Controls) ; port ISC_443
ISC_520: C465.D25F(Preamp) ; port ISC_520
ISC_521: C464.D9F(Outputs) C465.D9F(Outputs) C466.D9M(Outputs)
ISC_522: C464.D9F(Bias_Mon) C465.D9F(Bias_Mon) C466.D9M(Bias_Mon)
ISC_523: C464.D9M(From_DAC) C465.D9M(From_DAC) C466.D9F(From_DAC) C466.D9M(PZT_Bias_1)
ISC_524: C464.D37F(Binary_Controls) C465.D37F(Binary_Controls) C466.D37M(Binary_Controls)
ISC_533: C378.D15F(Controls) C382.D15M(Demod_RF_Levels_1)
ISC_534: C378.D9F(DAQ) ; port ISC_534
ISC_536: C466.D9F(PZT_Bias_1) ; port ISC_536
ISC_537: C466.D9F(PZT_Bias_2) ; port ISC_537
ISC_547: C466.D9M(From_DAC) ; port ISC_547
ISC_550: C378.TNC(LO1) ; port ISC_550
ISC_551: C378.TNC(LO2) ; port ISC_551
ISC_R5-RF9: C378.SMA(RFOut1) C386.SMA(RF1_PD1)
ISC_R5-RF10: C378.SMA(RFIn2) C386.SMA(RF2_PD2)
ISC_RF44-B/1: C386.TNC(RF2_PD2) ; port ISC_RF44-B/1
ISC_RF44-B/2: C386.TNC(RF1_PD2) ; port ISC_RF44-B/2
ISC_RF44-B/3: C386.TNC(TestIn1) ; port ISC_RF44-B/3
ISC_RF44-B/4: C386.TNC(TestOut2) ; port ISC_RF44-B/4
ISC_RF44-B/5: C386.TNC(DC_PD2) ; port ISC_RF44-B/5
ISC_SQ_506: C370.N(Sum) ; port ISC_SQ_506

Not connected (* = marked no-connect by the designer): C370 BNC(M1)* Conec-3(DC+/-17)*; C378 BNC(I-Mon1)* Conec-3(DC+/-18)*; C382 D9M(Demod_IQ_Wh._1)*; C464 BNC(A+)* Conec-3(DC+/-18)*; C465 BNC(A+)* Conec-3(DC+/-18)*

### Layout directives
Length: 25ft: ISC_307, ISC_439, ISC_440, ISC_441, ISC_442
Length: 8": ISC_R5-RF9, ISC_R5-RF10
Length: 2.5ft: ISC_533
Length: V?: ISC_520, ISC_RF44-B/1, ISC_RF44-B/2, ISC_RF44-B/3, ISC_RF44-B/4, ISC_RF44-B/5
Length: 2ft: ISC_521, ISC_522, ISC_523, ISC_524
DCC: D2400247: ISC_524
DCC: D2400251: ISC_523
DCC: D2400246: ISC_521, ISC_522
Length: 5ft: ISC_536, ISC_537

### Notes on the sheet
- ISC-R5 Rack (LSC)
- DCPD A & B
- (near C464) 1
- (near C465) 2
- DCPD C & D
- (near C466) 3
- (near C466) 4

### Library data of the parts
C370 = 3.125MHz Squeezer Pickoff: Serial: Sxxxxxxx; System: ISC
C378 = 2-Chan Demod: Serial: Sxxxxxxx; System: ISC
C382 = LSC Demod Concentrator: Serial: Sxxxxxxx; System: ISC
C386 = LSC RFPD PatchPanel Dual: Serial: Sxxxxxxx; System: ISC
C464 C465 = OMC DCPD Whitening Chassis: Serial: Sxxxxxxx; System: ISC
C466 = OMC DCPD Panel: Serial: Sxxxxxxx; System: ISC

## Sheet ISC_R5_SH2.SchDoc: ISC System Wiring Diagram
size B; DrawnBy: Filiberto Clara; Engineer: Filiberto Clara; Organization: LIGO Laboratory; Address1: California Institute of Technology; Address2: Massachusetts Institute of Technology; DocumentNumber: D1900511; Revision: V11; SheetNumber: 20; SheetTotal: 39
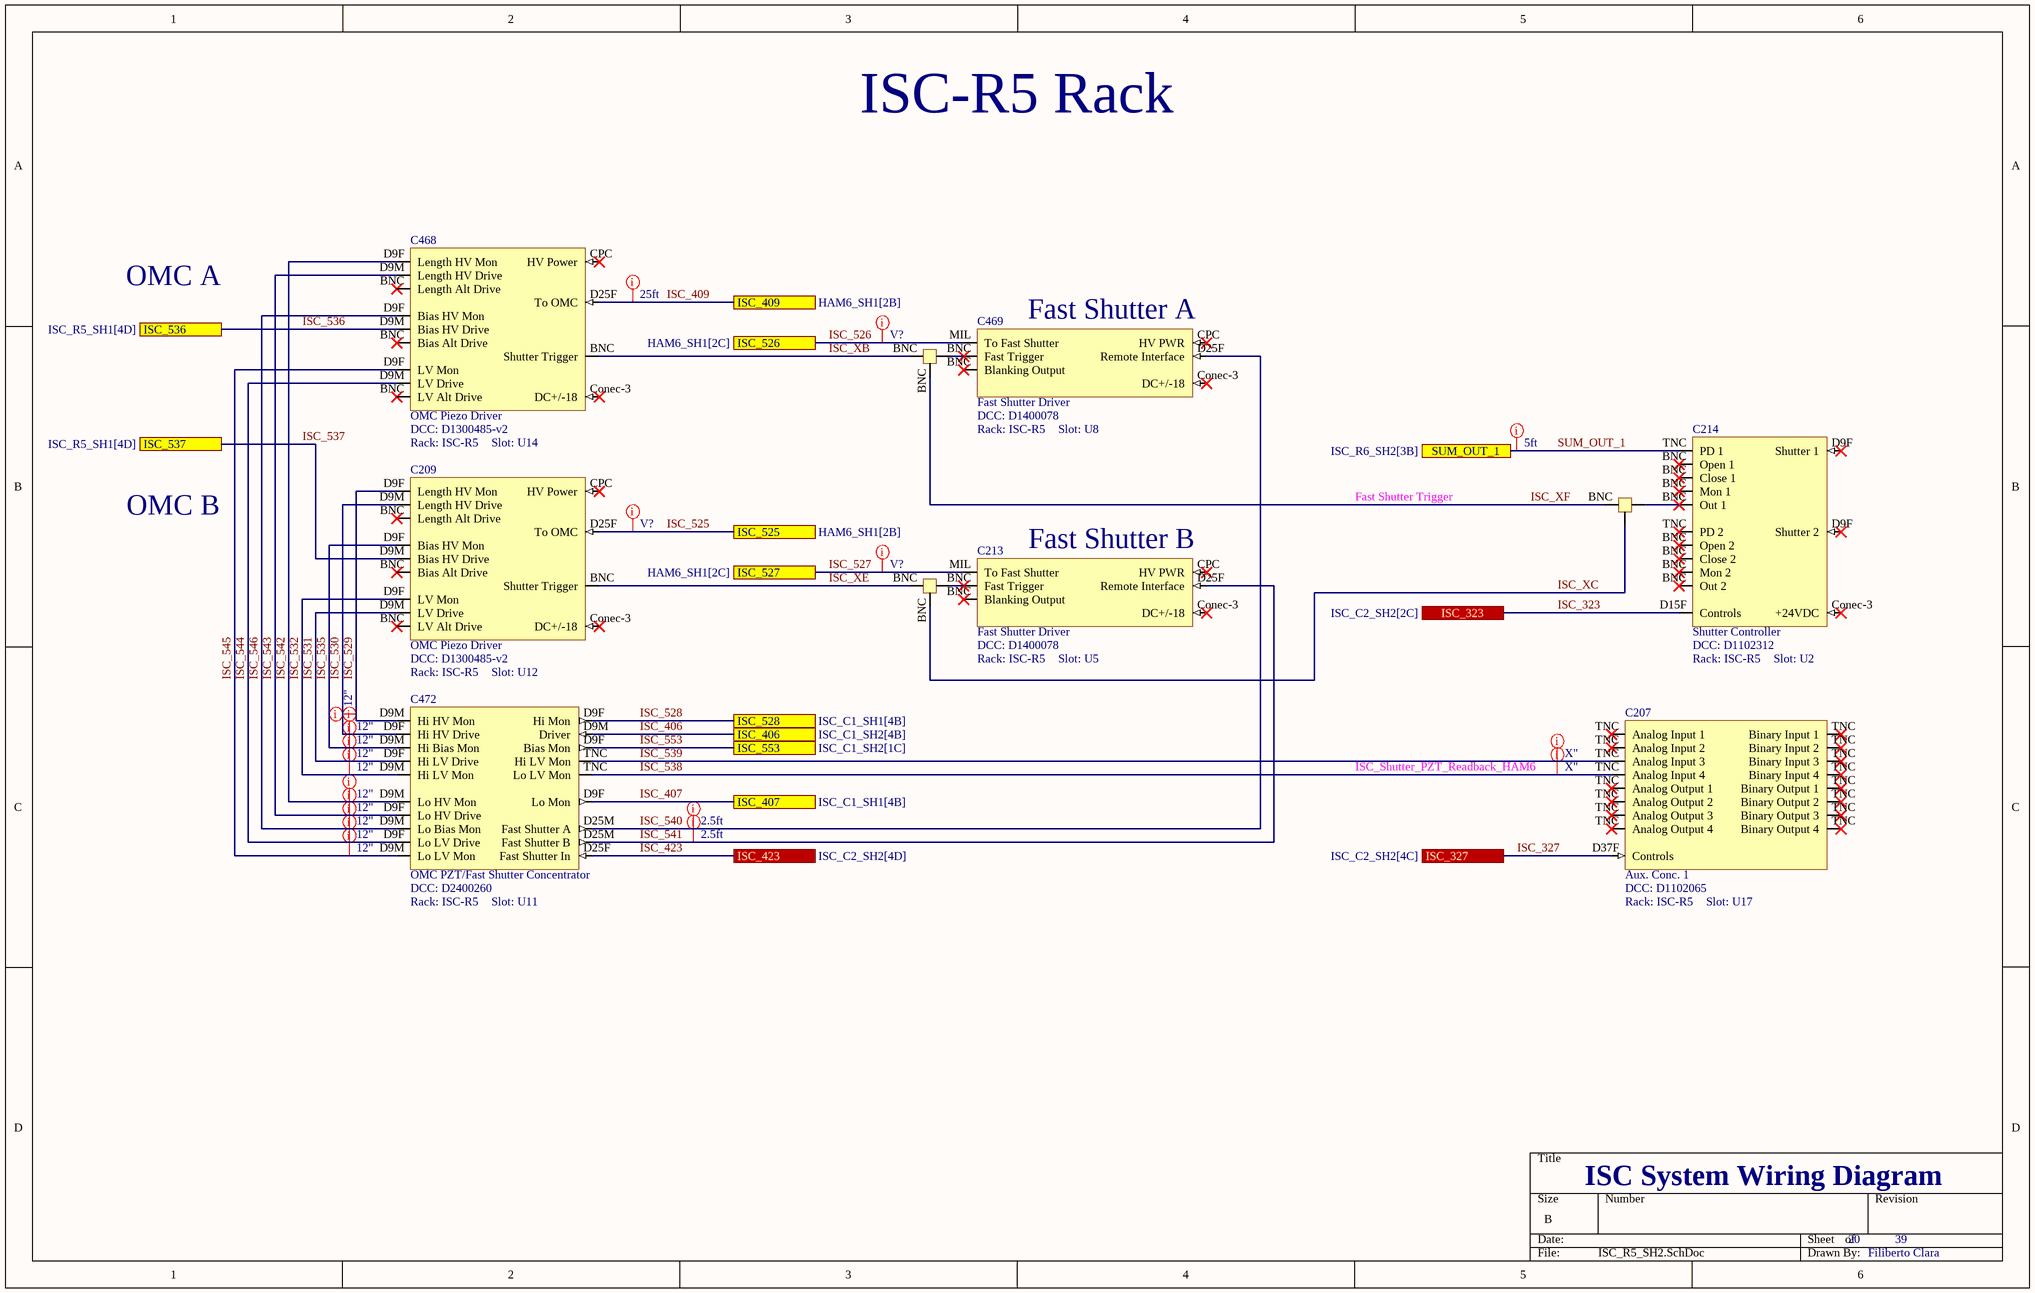
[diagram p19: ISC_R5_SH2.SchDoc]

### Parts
C207  Aux. Conc. 1  DCC: D1102065  Rack: ISC-R5  Slot: U17
C209  OMC Piezo Driver  DCC: D1300485-v2  Rack: ISC-R5  Slot: U12
C213  Fast Shutter Driver  DCC: D1400078  Rack: ISC-R5  Slot: U5
C214  Shutter Controller  DCC: D1102312  Rack: ISC-R5  Slot: U2
C281  Tee  (value not drawn)
C468  OMC Piezo Driver  DCC: D1300485-v2  Rack: ISC-R5  Slot: U14
C469  Fast Shutter Driver  DCC: D1400078  Rack: ISC-R5  Slot: U8
C470  Tee  (value not drawn)
C471  Tee  (value not drawn)
C472  OMC PZT/Fast Shutter Concentrator  DCC: D2400260  Rack: ISC-R5  Slot: U11

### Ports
ISC_323 (see ISC_C2_SH2[2C]), ISC_327 (see ISC_C2_SH2[4C]), ISC_406 (see ISC_C1_SH2[4B]), ISC_407 (see ISC_C1_SH1[4B]), ISC_409 (see HAM6_SH1[2B]), ISC_423 (see ISC_C2_SH2[4D]), ISC_525 (see HAM6_SH1[2B]), ISC_526 (see HAM6_SH1[2C]), ISC_527 (see HAM6_SH1[2C]), ISC_528 (see ISC_C1_SH1[4B]), ISC_536 (see ISC_R5_SH1[4D]), ISC_537 (see ISC_R5_SH1[4D]), ISC_553 (see ISC_C1_SH2[1C]), SUM_OUT_1 (see ISC_R6_SH2[3B])

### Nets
ISC_323: C214.D15F(Controls) ; port ISC_323
ISC_327: C207.D37F(Controls) ; port ISC_327
ISC_406: C472.D9M(Driver) ; port ISC_406
ISC_407: C472.D9F(Lo_Mon) ; port ISC_407
ISC_409: C468.D25F(To_OMC) ; port ISC_409
ISC_423: C472.D25F(Fast_Shutter_In) ; port ISC_423
ISC_525: C209.D25F(To_OMC) ; port ISC_525
ISC_526: C469.MIL(To_Fast_Shutter) ; port ISC_526
ISC_527: C213.MIL(To_Fast_Shutter) ; port ISC_527
ISC_528: C472.D9F(Hi_Mon) ; port ISC_528
ISC_529: C209.D9F(Length_HV_Mon) C472.D9M(Hi_HV_Mon)
ISC_530: C209.D9M(Length_HV_Drive) C472.D9F(Hi_HV_Drive)
ISC_531: C209.D9M(LV_Drive) C472.D9F(Hi_LV_Drive)
ISC_532: C209.D9F(LV_Mon) C472.D9M(Hi_LV_Mon)
ISC_535: C209.D9F(Bias_HV_Mon) C472.D9M(Hi_Bias_Mon)
ISC_536: C468.D9M(Bias_HV_Drive) ; port ISC_536
ISC_537: C209.D9M(Bias_HV_Drive) ; port ISC_537
ISC_538: C207.TNC(Analog_Input_4) C472.TNC(Lo_LV_Mon)
ISC_539: C207.TNC(Analog_Input_1) C472.TNC(Hi_LV_Mon)
ISC_540: C469.D25F(Remote_Interface) C472.D25M(Fast_Shutter_A)
ISC_541: C213.D25F(Remote_Interface) C472.D25M(Fast_Shutter_B)
ISC_542: C468.D9F(Length_HV_Mon) C472.D9M(Lo_HV_Mon)
ISC_543: C468.D9M(Length_HV_Drive) C472.D9F(Lo_HV_Drive)
ISC_544: C468.D9M(LV_Drive) C472.D9F(Lo_LV_Drive)
ISC_545: C468.D9F(LV_Mon) C472.D9M(Lo_LV_Mon)
ISC_546: C468.D9F(Bias_HV_Mon) C472.D9M(Lo_Bias_Mon)
ISC_553: C472.D9F(Bias_Mon) ; port ISC_553
ISC_XB: C468.BNC(Length_Alt_Drive) C470.BNC
ISC_XC: C281.BNC C471.BNC
ISC_XE: C209.BNC(Length_Alt_Drive) C281.BNC
ISC_XF: C470.BNC C471.BNC
SUM_OUT_1: C214.TNC(PD_1) ; port SUM_OUT_1
NetC213_BNC: C213.BNC(Fast_Trigger) C281.BNC
NetC214_BNC: C214.BNC(Open_1) C471.BNC
NetC469_BNC: C469.BNC(Fast_Trigger) C470.BNC

Not connected (* = marked no-connect by the designer): C209 Conec-3(DC+/-18)* CPC(HV_Power)*; C213 Conec-3(DC+/-18)* CPC(HV_PWR)*; C214 Conec-3(+24VDC)* D9F(Shutter_1)*; C468 Conec-3(DC+/-18)* CPC(HV_Power)*; C469 Conec-3(DC+/-18)* CPC(HV_PWR)*

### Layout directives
Length: X": ISC_538, ISC_539
Length: 5ft: SUM_OUT_1
Length: 12": ISC_529, ISC_530, ISC_531, ISC_532, ISC_535, ISC_542, ISC_543, ISC_544, ISC_545, ISC_546
Length: 25ft: ISC_409
Length: V?: ISC_525, ISC_526, ISC_527
Length: 2.5ft: ISC_540, ISC_541

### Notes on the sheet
- ISC-R5 Rack
- OMC A
- (near C469) Fast Shutter A
- OMC B
- Fast Shutter Trigger
- (near C213) Fast Shutter B
- ISC_Shutter_PZT_Readback_HAM6

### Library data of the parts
C207 = Aux. Conc. 1: Serial: Sxxxxxxx; System: ISC
C209 C468 = OMC Piezo Driver V2: Serial: Sxxxxxxx; System: ISC
C213 C469 = Fast Shutter Driver: Serial: Sxxxxxxx; System: ISC
C214 = Shutter Controller: Serial: Sxxxxxxx; System: ISC
C281 C470 C471 = TNC Tee: Tee (TNC); Serial: Sxxxxxxx; System: ISC; Rack: ISCT?; Slot: U?
C472 = OMC PZT/Fast Shutter Panel: Serial: Sxxxxxxx; System: ISC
